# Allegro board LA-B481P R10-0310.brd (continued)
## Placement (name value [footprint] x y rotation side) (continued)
PR105  210K_0402_1%  [R_0402]  127.13 12.95 270 top
PR106  100K_0402_5%  [R_0402]  133.12 14.27 180 top
PR107  0_0603_5%  [R_0603]  134.46 17.09 180 top
PR108  0_0603_5%  [R_0603]  125.44 17.09 180 top
PR109  4.7_1206_5%  [R_1206]  136.17 24.78 270 top
PR110  4.7_1206_5%  [R_1206]  121.19 24.39 270 top
PR111  2.2_1206_1%  [R_1206]  127.37 21.66 0 top
PR112  0_0402_5%  [R_0402]  122.79 13 270 top
PR113  0_0402_5%  [R_0402]  122.76 13.03 270 bottom
PR114  0_0402_5%  [R_0402]  124.62 12.09 90 top
PR115  2.2K_0402_5%  [R_0402]  123.7 13 270 top
PR116  402K_0402_1%  [R_0402]  125.5 13 270 top
PR200  2.2_0603_5%  [R_0603]  153.64 24.19 90 bottom
PR201  21K_0402_1%  [R_0402]  157.37 21.52 90 bottom
PR202  4.7_1206_5%  [R_1206]  149.19 11.5 0 bottom
PR203  5.1_0603_5%  [R_0603]  160.87 21.27 90 bottom
PR204  8.06K_0402_1%  [R_0402]  160.24 29.45 180 bottom
PR205  887K_0402_1%  [R_0402]  161.76 24.57 180 bottom
PR206  10K_0402_1%  [R_0402]  160.25 30.35 180 bottom
PR207  0_0402_5%  [R_0402]  161.82 26.48 180 bottom
PR208  0_0402_5%  [R_0402]  161.79 28.36 180 bottom
PR209  2.2_0603_5%  [R_0603]  160.37 23.32 180 top
PR210  10K_0402_5%  [R_0402]  161.78 23.7 180 bottom
PR300  2.55K_0402_1%  [R_0402]  169.68 108.46 90 bottom
PR301  4.7_0603_5%  [R_0603]  167.71 113.87 90 bottom
PR302  15K_0402_1%  [R_0402]  172.7 108.66 180 bottom
PR303  1M_0402_1%  [R_0402]  168.72 109.37 270 bottom
PR304  20K_0402_1%  [R_0402]  171.78 110.69 0 bottom
PR305  1M_0402_1%  [R_0402]  48.49 90.88 180 bottom
PR306  4.7_0603_5%  [R_0603]  51.34 93.99 90 bottom
PR307  13.7K_0402_1%  [R_0402]  50.45 88.14 90 bottom
PR308  10K_0402_5%  [R_0402]  47.58 91.77 0 bottom
PR309  20K_0402_1%  [R_0402]  49.56 89.05 270 bottom
PR400  20K_0402_1%  [R_0402]  62.66 92.84 270 bottom
PR401  4.7_0603_5%  [R_0603]  64.61 87.4 270 bottom
PR402  40.2K_0402_1%  [R_0402]  59.69 92.54 0 bottom
PR403  1M_0402_1%  [R_0402]  63.59 91.9 90 bottom
PR404  20K_0402_1%  [R_0402]  60.63 90.64 180 bottom
PR409  51.1K_0402_1%  [R_0402]  172.52 154.61 270 bottom
PR410  17.8K_0402_1%  [R_0402]  172.74 144.4 90 bottom
PR411  100K_0402_1%  [R_0402]  170.49 153.69 90 bottom
PR412  20K_0402_1%  [R_0402]  170.96 145.31 270 bottom
PR500  2.61K_0402_1%  [R_0402]  165.43 139.27 0 top
PR501  499_0402_1%  [R_0402]  168.18 138.11 180 bottom
PR502  2K_0402_1%  [R_0402]  162.59 139.98 270 top
PR503  137K_0402_1%  [R_0402]  163.47 137.21 90 bottom
PR504  2.05K_0402_1%  [R_0402]  166.14 137.23 90 bottom
PR505  2K_0402_1%  [R_0402]  165.18 139.03 180 bottom
PR506  0_0603_5%  [R_0603]  142.27 141.11 90 top
PR507  226_0402_1%  [R_0402]  161.65 139.01 180 top
PR508  21K_0402_1%  [R_0402]  162.58 137.21 90 bottom
PR509  11K_0402_1%  [R_0402]  164.69 138.13 270 top
PR510  1.91K_0402_1%  [R_0402]  161.57 139.09 270 bottom
PR511  2.2_0603_5%  [R_0603]  160.47 138.04 180 bottom
PR512  4.7_0603_5%  [R_0603]  136.93 140.73 270 top
PR513  3.65K_0603_1%  [R_0603]  166.14 141.62 270 top
PR514  61.9K_0402_1%  [R_0402]  164.28 132.84 0 top
PR515  3.83K_0402_1%  [R_0402]  167.97 135.97 180 bottom
PR516  0_0402_5%  [R_0402]  168 134.95 180 bottom
PR518  0_0603_5%  [R_0603]  158.21 134.31 180 bottom
PR519  1_0603_5%  [R_0603]  156.74 131.35 0 bottom
PR520  20_0402_1%  [R_0402]  167.93 133.77 180 bottom
PR521  16.9_0402_1%  [R_0402]  167.93 132.88 180 bottom
PR522  1.91K_0402_1%  [R_0402]  157.97 132.92 180 bottom
PR523  3.83K_0402_1%  [R_0402]  167 131.1 0 bottom
PR524  0_0402_5%  [R_0402]  167.92 129.31 180 bottom
PR525  499_0402_1%  [R_0402]  167.03 131.1 90 top
PR526  73.2_0402_1%  [R_0402]  167.93 132.88 180 top
PR527  73.2_0402_1%  [R_0402]  167.93 133.77 180 top
PR528  0_0603_5%  [R_0603]  156.73 125.7 180 top
PR529  61.9K_0402_1%  [R_0402]  167.92 130.2 180 bottom
PR530  1.91K_0402_1%  [R_0402]  161.69 128.44 270 bottom
PR531  2.2_0603_5%  [R_0603]  160.72 127.8 180 bottom
PR532  4.7_0603_5%  [R_0603]  153.86 121.38 180 top
PR533  2K_0402_1%  [R_0402]  164.35 126.65 0 bottom
PR534  64.9K_0402_1%  [R_0402]  162.58 127.52 90 bottom
PR535  2.61K_0402_1%  [R_0402]  165.64 127.66 270 top
PR536  3.65K_0603_1%  [R_0603]  166.78 126.5 90 top
PR538  499_0402_1%  [R_0402]  167.11 128.34 180 bottom
PR539  2K_0402_1%  [R_0402]  160.68 127.15 270 top
PR540  191_0402_1%  [R_0402]  161.57 127.15 270 top
PR541  11K_0402_1%  [R_0402]  164.75 127.66 270 top
PR542  1.78K_0402_1%  [R_0402]  167.11 127.33 180 bottom
PR543  137K_0402_1%  [R_0402]  165.26 127.54 180 bottom
PR700  0.01_1206_1%  [R_1206_4P-D]  147.6 159.04 270 bottom
PR701  200K_0402_1%  [R_0402]  143.67 160.3 270 top
PR702  200K_0402_1%  [R_0402]  136.68 163.6 270 top
PR703  150K_0402_1%  [R_0402]  142.78 159.38 90 top
PR704  10_0402_5%  [R_0402]  167.64 167.49 180 top
PR705  10_0402_5%  [R_0402]  167.64 166.6 180 top
PR706  200K_0402_1%  [R_0402]  170.07 164.72 90 top
PR707  10_1206_1%  [R_1206]  164.79 177.24 0 top
PR708  47K_0402_1%  [R_0402]  170.06 162.94 90 top
PR709  4.7_0603_5%  [R_0603]  168.11 177.11 180 bottom
PR710  100K_0402_1%  [R_0402]  176 174.45 180 top
PR711  232K_0402_1%  [R_0402]  170.06 167.41 270 top
PR712  200K_0402_5%  [R_0402]  141.33 159.59 180 top
PR713  0_0603_5%  [R_0603]  164.81 173.05 0 bottom
PR714  100K_0402_1%  [R_0402]  173.89 164.74 270 top
PR715  49.9K_0402_1%  [R_0402]  171.17 170.46 270 bottom
PR716  158K_0402_1%  [R_0402]  175.09 173.43 0 top
PR717  0_0402_5%  [R_0402]  176 171.91 180 top
PR718  10K_0402_5%  [R_0402]  143.69 165 270 top
PR719  0_0402_5%  [R_0402]  176 171.02 180 top
PR720  0.01_1206_1%  [R_1206_4P-D]  149.8 181.86 0 bottom
PR721  4.7_1206_5%  [R_1206]  149.48 174.03 270 bottom
PR722  100_0402_1%  [R_0402]  176 170.08 180 top
PR723  4.7K_0402_5%  [R_0402]  174.15 167.79 270 top
PR724  10_0402_5%  [R_0402]  172.7 178.51 180 top
PR725  221K_0402_1%  [R_0402]  172.24 166.88 90 top
PR726  100_0402_5%  [R_0402]  173.43 176.22 0 top
PR727  287K_0402_1%  [R_0402]  171.22 166.88 90 top
PR728  28.7K_0402_1%  [R_0402]  173.26 166.88 90 top
PR729  63.4K_0402_1%  [R_0402]  172.19 165.94 180 top
PR730  3.3K_1206_5%~D  [R_1206]  133.38 163.84 270 top
PU100  -  [TPS51225CRUKR_QFN20_3X3]  128.43 14.55 0 top
PU200  -  [RT8207MZQW_WQFN20_3X3]  156.49 27.62 0 bottom
PU300  -  [SY8032ABC_SOT23-6]  168.02 110.63 90 bottom
PU301  -  [SY8032ABC_SOT23-6]  49.88 92.59 0 bottom
PU400  -  [SY8032ABC_SOT23-6]  64.29 90.64 270 bottom
PU402  -  [APL5930KAI-TRG_SO8]  172.23 146.89 180 bottom
PU500  -  [ISL95833HRTZ-T_TQFN32_4X4]  165.12 134.24 270 bottom
PU700  ISL88731CHRTZ-T TQFN 28P PWM  [BQ24745RHDR_QFN28_5X5]  169.39 169.89 0 top
Q8  -  [2N7002K_SOT23-3]  163.71 22.68 270 top
Q14  -  [DMN66D0LDW-7_SOT363-6]  14.78 112.66 180 bottom
Q50  -  [2N7002K_SOT23-3]  175.01 69.29 270 top
Q57  -  [MESS138W-G_SOT323-3]  18 110.18 90 top
Q58  -  [MESS138W-G_SOT323-3]  18 107.77 90 top
Q70  -  [2N7002K_SOT23-3]  65.46 101.37 270 bottom
Q71  -  [2N7002K_SOT23-3]  65.46 97.31 270 bottom
Q2307  -  [2N7002K_SOT23-3]  156.98 33.35 270 top
Q2308  -  [2N7002K_SOT23-3]  68.99 29.77 0 top
Q2309  -  [DMN66D0LDW-7_SOT363-6]  208.42 157.23 0 bottom
QA5  -  [DMN66D0LDW-7_SOT363-6]  29.25 17.95 180 top
QA6  -  [DMN66D0LDW-7_SOT363-6]  27.61 14.48 270 top
QC1  -  [MESS138W-G_SOT323-3]  126.84 123.77 90 top
QC2  -  [MESS138W-G_SOT323-3]  106.71 139.33 0 top
QC3  -  [MESS138W-G_SOT323-3]  118.39 136.79 0 top
QC4  -  [MESS138W-G_SOT323-3]  120.93 136.79 0 top
QD18  -  [2N7002K_SOT23-3]  57.9 16.58 90 top
QD19  -  [2N7002K_SOT23-3]  61.48 16.6 270 top
QD20  -  [2N7002K_SOT23-3]  68.46 16.58 270 top
QM30  -  [2N7002K_SOT23-3]  102.42 147.33 90 top
QS2  SI3456BDV-T1-E3 1N TSOP6  [SI3456BDV-T1-E3_TSOP6]  222.35 108.04 90 top
QS3  -  [2N7002KW_SOT323-3]  222.19 107.77 270 bottom
QX1  -  [2N7002KW_SOT323-3]  214.32 176.48 90 top
QX2  -  [SI3457CDV-T1-GE3_TSOP6]  221.59 175.15 90 top
QX6  -  [DMN66D0LDW-7_SOT363-6]  198.85 156.17 270 top
R3  4.7K_0402_5%  [R_0402]  78.96 87.31 90 top
R4  4.7K_0402_5%  [R_0402]  80.36 95.02 270 top
R5  4.7K_0402_5%  [R_0402]  97.93 143.19 0 top
R6  4.7K_0402_5%  [R_0402]  82.77 95.02 270 top
R7  4.7K_0402_5%  [R_0402]  77.88 95.02 270 top
R8  4.7K_0402_5%  [R_0402]  102.34 138.95 180 top
R10  100K_0402_5%  [R_0402]  161.7 22.22 90 top
R13  4.7K_0402_5%  [R_0402]  79.12 84.95 0 top
R14  4.7K_0402_5%  [R_0402]  73.5 84.2 90 top
R15  0_0402_5%  [R_0402]  60.67 84.29 270 top
R16  100K_0402_5%  [R_0402]  167.54 22.22 90 top
R17  0_0402_5%  [R_0402]  59.66 81.6 90 top
R18  0_0402_5%  [R_0402]  82.27 85.08 180 top
R19  0_0402_5%  [R_0402]  81.37 84.14 0 top
R20  0_0402_5%  [R_0402]  74.82 84.73 0 top
R21  0_0402_5%  [R_0402]  76.79 83.84 180 top
R121  100K_0402_5%  [R_0402]  14.18 111.58 0 bottom
R122  100K_0402_5%  [R_0402]  14.18 115.64 0 bottom
R376  10K_0402_5%  [R_0402]  15.9 113.66 90 bottom
R377  10K_0402_5%  [R_0402]  208.44 153.41 90 bottom
R378  10K_0402_5%  [R_0402]  99.39 94.82 0 top
R379  10K_0402_5%  [R_0402]  106.45 134.49 90 top
R380  10K_0402_5%  [R_0402]  107.34 134.49 90 top
R432  0_0402_5%  [R_0402]  109.93 145.74 0 top
R434  0_0402_5%  [R_0402]  109.93 146.76 0 top
R488  10K_0402_5%  [R_0402]  189.39 47.88 90 top
R489  10K_0402_5%  [R_0402]  190.66 44.96 90 top
R696  10K_0402_5%  [R_0402]  177.02 61.03 180 top
R697  10K_0402_5%  [R_0402]  178.79 64.97 180 top
R926  120K_0402_5%  [R_0402]  109.12 31.27 270 bottom
R927  100K_0402_5%  [R_0402]  106.07 30.35 90 bottom
R1022  0_0603_5%  [R_0603]  99.15 123.01 180 top
R1023  0_0603_5%  [R_0603]  122.52 123.39 0 top
R1024  10K_0402_5%  [R_0402]  81.26 89.24 180 top
R1027  4.7K_0402_1%  [R_0402]  83.98 66.93 90 top
R1028  4.7K_0402_1%  [R_0402]  84.99 66.93 90 top
R1029  4.7K_0402_1%  [R_0402]  124.72 57.77 90 top
R1030  4.7K_0402_1%  [R_0402]  123.7 57.77 90 top
R1033  10K_0402_5%  [R_0402]  74.2 89.22 90 top
R1045  0_0603_5%  [R_0603]  57.88 51.48 180 top
R1046  10K_0402_5%  [R_0402]  56.04 60.4 270 top
R1047  100K_0402_5%  [R_0402]  51.84 50.01 90 top
R1048  2.7K_0402_1%  [R_0402]  48.44 53.29 180 top
R1049  100K_0402_5%  [R_0402]  54.89 50.01 90 top
R1050  10K_0402_5%  [R_0402]  53.88 50.01 90 top
R1051  10K_0402_5%  [R_0402]  56.04 57.53 90 top
R1052  470_0603_5%  [R_0603]  67.53 97.31 0 bottom
R1055  82K_0402_5%  [R_0402]  60.02 101.29 0 top
R1056  47K_0402_5%  [R_0402]  60.02 104.34 0 top
R1061  10K_0402_5%  [R_0402]  67.21 102.94 90 bottom
R1071  619_0402_1%  [R_0402]  16.11 101.67 180 top
R1072  619_0402_1%  [R_0402]  16.11 100.66 180 top
R1073  619_0402_1%  [R_0402]  15.85 104.47 180 top
R1074  619_0402_1%  [R_0402]  15.85 103.45 180 top
R1075  619_0402_1%  [R_0402]  16.11 98.88 180 top
R1076  619_0402_1%  [R_0402]  16.11 97.86 180 top
R1077  619_0402_1%  [R_0402]  16.11 95.83 180 top
R1078  619_0402_1%  [R_0402]  16.11 94.82 180 top
R1088  0_0402_5%  [R_0402]  88.11 107.57 135 bottom
R1089  0_0402_5%  [R_0402]  88.86 107.07 45 bottom
R2314  22_0603_5%  [R_0603]  146.02 61.03 180 top
R2315  470_0603_5%  [R_0603]  66.2 31.25 270 top
R2354  0_0402_5%  [R_0402]  186.72 47.88 90 top
R2355  0_0402_5%  [R_0402]  44.22 26.79 90 top
RA1  100K_0402_5%  [R_0402]  27.96 23.98 270 top
RA2  100K_0402_5%  [R_0402]  30.6 23.99 270 top
RA3  10K_0402_5%  [R_0402]  27.46 20.6 270 top
RA4  0_0402_5%  [R_0402]  26.57 20.6 270 top
RA5  470K_0402_5%  [R_0402]  32.16 25.3 270 top
RA6  10K_0402_5%  [R_0402]  29.71 23.98 270 top
RA7  10K_0402_5%  [R_0402]  28.83 23.98 270 top
RA8  0_0402_5%  [R_0402]  51.73 18.55 180 top
RA9  0_0402_5%  [R_0402]  51.73 17.6 180 top
RA10  0_0402_5%  [R_0402]  33.94 25.3 270 top
RA12  0_0402_5%  [R_0402]  33.05 25.3 270 top
RA19  10K_0402_5%  [R_0402]  192.51 46.05 180 top
RA28  0_0402_5%  [R_0402]  36.3 19 180 top
RA29  0_0603_5%  [R_0603]  23.02 20.97 90 top
RA30  0_0603_5%  [R_0603]  25.43 11.95 270 top
RA31  0_0603_5%  [R_0603]  25.94 23.06 90 top
RA32  0_0603_5%  [R_0603]  35.21 12.84 270 top
RA34  200K_0402_1%  [R_0402]  37.57 24.33 180 top
RA51  39.2K_0402_1%  [R_0402]  37.57 23.44 180 top
RA53  2.2K_0402_5%  [R_0402]  37.01 21.28 180 top
RA55  8.2_0402_1%  [R_0402]  24.74 14.93 180 bottom
RA56  8.2_0402_1%  [R_0402]  24.74 18.24 180 bottom
RA79  1K_0402_1%  [R_0402]  41.05 28.52 90 top
RA80  1K_0402_1%  [R_0402]  35.87 15.26 270 top
RA81  10K_0402_5%  [R_0402]  40.1 26.67 90 top
RA82  1K_0402_1%  [R_0402]  34.97 15.26 270 top
RA83  10K_0402_5%  [R_0402]  23.83 15.82 0 bottom
RA84  10K_0402_5%  [R_0402]  23.83 17.35 0 bottom
RA130  22_0402_5%  [R_0402]  122.13 130.88 0 bottom
RA153  20K_0402_1%  [R_0402]  34.88 23.44 0 top
RA154  100K_0402_5%  [R_0402]  39.53 15.11 90 top
RA155  100K_0402_5%  [R_0402]  38.51 24.38 90 top
RA165  4.7K_0402_5%  [R_0402]  44.62 15.77 270 top
RA166  4.7K_0402_5%  [R_0402]  43.74 15.77 270 top
RA1109  2.2K_0402_5%  [R_0402]  37.01 22.3 180 top
RC1  100K_0402_5%  [R_0402]  121.22 110.47 135 top
RC2  100K_0402_5%  [R_0402]  121.85 111.11 135 top
RC3  23.2_0402_1%  [R_0402]  119.95 109.2 135 top
RC4  29.4_0402_1%  [R_0402]  120.58 109.84 135 top
RC5  162_0402_1%  [R_0402]  119.31 108.57 135 top
RC6  4.7K_0402_1%  [R_0402]  126.04 105.7 90 bottom
RC7  4.7K_0402_1%  [R_0402]  125.15 105.7 90 bottom
RC8  2.2K_0402_5%  [R_0402]  108.48 109.4 225 top
RC9  402_0402_1%  [R_0402]  108.94 123.71 225 top
RC10  10K_0402_5%  [R_0402]  100.3 102.11 135 bottom
RC11  10K_0402_5%  [R_0402]  100.42 103.52 315 bottom
RC12  402_0402_1%  [R_0402]  112.28 123.64 45 top
RC13  402_0402_1%  [R_0402]  110.21 123.7 135 top
RC14  49.9_0402_1%  [R_0402]  120.48 128.91 45 bottom
RC15  33.2_0402_1%  [R_0402]  95.98 105.68 225 bottom
RC16  10K_0402_5%  [R_0402]  119.1 120.94 135 top
RC17  10K_0402_5%  [R_0402]  125.76 122.43 90 top
RC18  10K_0402_5%  [R_0402]  105.87 136.35 0 top
RC19  1M_0402_5%  [R_0402]  101.06 128.41 225 bottom
RC20  4.7K_0402_5%  [R_0402]  64.16 84.1 270 top
RC21  2.2K_0402_5%  [R_0402]  99.65 110 315 top
RC22  47.5_0402_1%  [R_0402]  103.09 122.15 315 top
RC23  4.02K_0402_1%  [R_0402]  104.29 120.88 315 top
RC24  0_0402_5%  [R_0402]  114.27 135.39 135 bottom
RC25  200_0402_5%  [R_0402]  101.02 111.36 135 top
RC26  100K_0402_5%  [R_0402]  92.48 113.31 270 top
RC27  73.2_0402_1%  [R_0402]  94.96 102.37 45 bottom
RC28  20_0402_1%  [R_0402]  96.87 104.28 225 bottom
RC29  16.9_0402_1%  [R_0402]  98.9 106.06 225 bottom
RC30  10K_0402_5%  [R_0402]  85.04 85.93 0 top
RC31  10M_0402_5%  [R_0402]  90.84 115.31 315 bottom
RC32  49.9_0402_1%  [R_0402]  105.49 113.74 0 top
RC33  1K_0402_5%  [R_0402]  183.04 110.01 270 bottom
RC34  20K_0402_1%  [R_0402]  87.51 109.54 315 bottom
RC35  20K_0402_1%  [R_0402]  91.91 111.27 315 bottom
RC36  3.3K_0402_5%  [R_0402]  70.06 82.37 0 top
RC37  3.3K_0402_5%  [R_0402]  83.67 80.59 180 top
RC38  3.3K_0402_5%  [R_0402]  70.06 80.59 0 top
RC39  33_0402_5%  [R_0402]  82.76 79.58 0 top
RC40  1.24K_0402_1%  [R_0402]  101.76 119.64 45 top
RC41  1K_0402_1%  [R_0402]  96.64 114.21 45 top
RC42  1K_0402_1%  [R_0402]  98.64 115.57 45 top
RC43  10K_0402_5%  [R_0402]  112.47 136.22 0 top
RC44  10K_0402_5%  [R_0402]  93.19 107.84 225 bottom
RC45  45.3_0402_1%  [R_0402]  98.9 117.75 225 top
RC46  10K_0402_5%  [R_0402]  94.19 108.84 45 bottom
RC47  0_0402_5%  [R_0402]  103.03 119.66 225 top
RC48  10K_0402_5%  [R_0402]  113.39 135.33 180 top
RC49  45.3_0402_1%  [R_0402]  89.06 118.95 315 bottom
RC50  49.9_0402_1%  [R_0402]  114.58 135.53 270 top
RC51  22_0402_5%  [R_0402]  120.49 134 225 bottom
RC52  22_0402_5%  [R_0402]  119.73 134.64 225 bottom
RC53  4.7K_0402_5%  [R_0402]  103.71 138.63 0 top
RC54  0_0402_5%  [R_0402]  118.77 113.87 0 top
RC55  100_0402_1%  [R_0402]  108.23 135.41 270 top
RC56  100_0402_1%  [R_0402]  108.74 113.05 270 top
RC57  49.9_0402_1%  [R_0402]  107.67 124.53 180 top
RC58  100_0402_1%  [R_0402]  106.52 109.73 135 top
RC59  49.9_0402_1%  [R_0402]  123.28 126.24 45 bottom
RC60  10K_0402_5%  [R_0402]  119.28 131.54 225 bottom
RC61  200_0402_5%  [R_0402]  54 80.54 270 top
RC62  1K_0402_5%  [R_0402]  63.15 81.3 270 top
RC63  51_0402_5%  [R_0402]  65.18 81.3 270 top
RC64  51_0402_5%  [R_0402]  101.94 112.4 45 top
RC65  51_0402_5%  [R_0402]  100.39 110.72 135 top
RC66  33_0402_5%  [R_0402]  123.58 128.25 225 bottom
RC67  100K_0402_5%  [R_0402]  102.85 97.99 180 top
RC68  10K_0402_5%  [R_0402]  127.98 122.83 315 bottom
RC69  33_0402_5%  [R_0402]  122.32 129.51 225 bottom
RC70  33_0402_5%  [R_0402]  122.96 128.87 225 bottom
RC71  33_0402_5%  [R_0402]  126.62 126.74 135 bottom
RC99  0_0402_1%  [R0402_0OHM]  82.76 81.61 0 top
RC100  0_0402_1%  [R0402_0OHM]  110.62 113.21 225 top
RD3  470_0402_5%  [R_0402]  93.6 60.82 90 top
RD4  0_0402_1%  [R0402_0OHM]  124.72 61.73 270 top
RD5  0_0402_1%  [R0402_0OHM]  92.59 60.82 90 top
RD6  10K_0402_5%  [R_0402]  143.44 68.77 0 top
RD7  10K_0402_5%  [R_0402]  143.44 69.78 0 top
RD8  0_0402_1%  [R0402_0OHM]  122.1 64.7 0 top
RD9  0_0402_1%  [R0402_0OHM]  122.43 63.31 0 top
RD14  680_0402_1%  [R_0402]  34.27 10.49 180 top
RD15  390_0402_5%  [R_0402]  43.98 10.74 180 top
RD17  390_0402_5%  [R_0402]  50.52 11.89 180 top
RD18  680_0402_1%  [R_0402]  57.93 12.9 0 top
RD45  100K_0402_5%  [R_0402]  59.16 22.55 180 top
RD46  100K_0402_5%  [R_0402]  58.82 13.9 180 top
RD47  100K_0402_5%  [R_0402]  65.32 16.33 90 top
RD48  0_0402_5%  [R_0402]  58.25 23.44 0 top
RD49  0_0402_5%  [R_0402]  60.68 18.11 180 top
RD50  100K_0402_5%  [R_0402]  72.55 15.62 90 top
RD51  0_0402_5%  [R_0402]  56.92 13.87 270 top
RD52  100K_0402_5%  [R_0402]  55.91 13.87 270 top
RD53  0_0402_5%  [R_0402]  73.56 15.62 90 top
RE1  10K_0402_5%  [R_0402]  175.21 57.22 0 top
RE3  100K_0402_1%  [R_0402]  192.48 71.32 0 top
RE4  0_0805_5%  [R_0805]  198.66 46.47 90 top
RE5  33K_0402_1%  [R_0402]  193.4 70.43 180 top
RE6  0_0805_5%  [R_0805]  196.88 46.47 90 top
RE7  0_0402_5%  [R_0402]  197.64 70.38 270 top
RE8  47K_0402_5%  [R_0402]  199.85 54.81 0 top
RE9  4.7K_0402_5%  [R_0402]  186.59 70.38 270 top
RE10  4.7K_0402_5%  [R_0402]  185.58 70.38 270 top
RE11  100K_0402_5%  [R_0402]  179.18 49.86 180 top
RE12  0_0402_5%  [R_0402]  178.92 55.07 180 top
RE13  0_0402_5%  [R_0402]  176 64.59 180 top
RE14  0_0402_5%  [R_0402]  189.64 44.96 90 top
RE15  0_0402_5%  [R_0402]  190.15 70.38 270 top
RE16  0_0402_5%  [R_0402]  189.13 70.38 270 top
RE17  0_0402_5%  [R_0402]  156.7 81.1 180 top
RE18  10K_0402_5%  [R_0402]  195.48 48.79 270 top
RE19  0_0402_5%  [R_0402]  159.49 81.1 180 top
RE20  0_0402_5%  [R_0402]  162.28 81.1 180 top
RE21  0_0402_5%  [R_0402]  165.08 81.1 180 top
RE36  43_0402_1%  [R_0402]  178.01 61.92 0 top
RE37  0_0402_1%  [R0402_0OHM]  187.99 70.38 270 top
RE43  43_0402_1%  [R_0402]  178.92 56.72 180 top
RE44  0_0402_1%  [R0402_0OHM]  176 65.61 180 top
RE47  100K_0402_5%  [R_0402]  178.21 63.78 270 top
RE49  100K_0402_5%  [R_0402]  194.54 27.57 180 top
RE50  10K_0402_5%  [R_0402]  50.91 105.23 180 bottom
RE60  240_0402_1%  [R_0402]  227.99 156.33 90 bottom
RE71  10K_0402_5%  [R_0402]  176.94 59.08 270 top
RG1  330_0402_5%  [R_0402]  70.26 42.7 270 top
RG2  0_0402_5%  [R_0402]  64.67 42.7 270 top
RG5  33_0402_5%  [R_0402]  68.23 35.58 270 top
RG6  0_0402_5%  [R_0402]  67.21 35.58 270 top
RG8  0_0402_5%  [R_0402]  70.26 34.67 90 top
RG10  0_0402_5%  [R_0402]  102.33 129.68 225 bottom
RG11  0_0402_5%  [R_0402]  35.97 75.82 90 bottom
RI1  0_0805_5%  [R_0805]  23.27 66.53 90 top
RI2  0_0805_5%  [R_0805]  26.19 51.72 270 bottom
RI3  0_0805_5%  [R_0805]  25.56 41.9 90 bottom
RI4  0_0805_5%  [R_0805]  23.31 64.97 0 top
RI5  0_0805_5%  [R_0805]  25.85 53.16 0 bottom
RI6  0_0805_5%  [R_0805]  25.47 37.41 0 bottom
RL19  75_0603_5%  [R_0603]  20.29 85.54 270 top
RL20  75_0603_5%  [R_0603]  20.29 81.73 90 top
RL27  100K_0402_5%  [R_0402]  48.97 79.32 0 bottom
RL28  0_0805_5%  [R_0805]  47.44 75.26 0 bottom
RL31  2.49K_0402_1%  [R_0402]  35.08 79.37 90 bottom
RL33  1K_0402_5%  [R_0402]  45.06 87.32 180 bottom
RL34  10K_0402_5%  [R_0402]  43.03 83.39 180 bottom
RL35  15K_0402_5%  [R_0402]  45.06 86.43 180 bottom
RL36  10K_0402_5%  [R_0402]  41.56 80.92 270 bottom
RL38  10K_0402_5%  [R_0402]  49.89 78.43 180 bottom
RL40  10K_0402_5%  [R_0402]  50.7 80.52 90 bottom
RM11  100K_0402_5%  [R_0402]  115.09 147.7 90 top
RM13  1K_0402_1%  [R_0402]  115.98 148.61 270 top
RM25  0_0805_1%  [R0805_0OHM]  120.16 147.98 180 top
RM26  0_0805_1%  [R0805_0OHM]  96 148.47 180 top
RM110  10K_0402_5%  [R_0402]  104.17 148.68 270 top
RP15  2.2K_0804_8P4R_5%  [RP_0804_8P4R]  18.71 111.65 270 bottom
RP36  2.2K_0804_8P4R_5%  [RP_0804_8P4R]  189.4 72.27 90 top
RP54  8.2K_8P4R_5%  [RP_0804_8P4R]  123.1 135.13 90 top
RP56  2.2K_8P4R_5%  [RP_0804_8P4R]  210.78 162.01 0 bottom
RP63  10K_0804_8P4R_5%  [RP_0804_8P4R]  109.77 135.39 90 top
RP65  10K_0804_8P4R_5%  [RP_0804_8P4R]  104.03 109.74 270 top
RP66  51_0804_8P4R_5%  [RP_0804_8P4R]  98.06 113.39 45 top
RP67  22_0804_8P4R_5%  [RP_0804_8P4R]  96.55 107.09 45 bottom
RP68  4.7K_0804_8P4R_5%  [RP_0804_8P4R]  117.25 134.52 45 bottom
RR1  6.19K_0402_1%  [R_0402]  175.21 18.08 270 top
RR2  22_0402_5%  [R_0402]  178.21 27.11 90 top
RR3  22_0402_5%  [R_0402]  180.88 20.94 0 top
RS6  470K_0402_5%  [R_0402]  222.36 105.74 180 bottom
RS7  0_0402_5%  [R_0402]  220.68 53.92 0 bottom
RS8  0_0402_5%  [R_0402]  220.68 52.91 0 bottom
RS9  100K_0402_5%  [R_0402]  216.36 115.77 0 top
RS09  0_0402_5%  [R_0402]  221.44 112.09 0 bottom
RS10  0_0402_5%  [R_0402]  221.44 117.17 0 bottom
RS11  0_0805_5%  [R_0805]  217.96 113.83 270 top
RS12  0_0805_5%  [R_0805]  219.74 113.83 270 top
RT1  0_0805_1%  [R0805_0OHM]  198.75 169.87 180 bottom
RT2  4.7K_0402_5%  [R_0402]  210.72 156.16 270 bottom
RT3  4.7K_0402_5%  [R_0402]  210.72 157.4 90 bottom
RT9  0_0402_5%  [R0402_0OHM]  200.44 157.67 90 bottom
RT11  0_0402_5%  [R0402_0OHM]  199.55 157.67 90 bottom
RT12  4.7K_0402_5%  [R_0402]  211.74 157.4 90 bottom
RT14  0_0402_5%  [R_0402]  195.18 164.16 180 bottom
RT15  0_0402_5%  [R_0402]  195.18 165.05 180 bottom
RT16  100K_0402_5%  [R_0402]  208.23 158.32 0 bottom
RT17  100K_0402_5%  [R_0402]  207.29 155.32 90 bottom
RT18  100K_0402_5%  [R_0402]  206.28 156.23 270 bottom
RT19  100K_0402_5%  [R_0402]  202.64 165.17 0 top
RT20  4.7K_0402_5%  [R_0402]  211.74 156.16 270 bottom
RT21  0_0402_5%  [R_0402]  200.44 156.68 270 bottom
RT22  0_0402_5%  [R_0402]  199.55 156.68 270 bottom
RT331  0_0603_5%  [R_0603]  194.97 161.3 90 bottom
RV31  0_0402_5%  [R_0402]  210.47 176.02 90 top
RV32  0_0402_5%  [R_0402]  211.48 176.02 90 top
RV54  0_0603_1%  [R0603_0OHM]  50.57 25.09 180 top
RV59  0_0603_1%  [R0603_0OHM]  36.6 11.44 90 top
RV299  0_0805_5%  [R_0805]  215.67 158.61 90 bottom
RV300  0_0805_5%  [R_0805]  214.32 168.1 0 bottom
RV301  0_0805_5%  [R_0805]  223.08 175.59 0 top
RX1  0_0402_5%  [R_0402]  18.7 93.09 90 top
RX2  100K_0402_5%  [R_0402]  216.44 176.53 90 top
RX3  100K_0402_5%  [R_0402]  215.55 177.44 270 top
RX4  0_0402_5%  [R_0402]  193.07 55.37 90 bottom
RX5  12K_0402_1%  [R_0402]  201.7 158.37 90 bottom
RX6  3.3K_0402_5%  [R_0402]  202.64 164.29 0 top
RX7  0_0402_5%  [R_0402]  218.47 163.83 90 bottom
RX8  0_0402_5%  [R_0402]  218.47 162.84 270 bottom
RX9  10K_0402_5%  [R_0402]  221.34 172.79 180 top
RX12  10K_0402_5%  [R_0402]  15.09 110.56 180 bottom
RX18  0_0402_5%  [R_0402]  213.47 172.79 180 top
RX19  0_0402_1%  [R0402_0OHM]  214.33 172.79 0 top
RX20  0_0402_1%  [R0402_0OHM]  212.55 173.81 0 top
RX21  0_0402_5%  [R_0402]  218.65 167.1 90 bottom
RX22  0_0402_5%  [R_0402]  217.76 167.1 90 bottom
RX23  0_0402_5%  [R_0402]  215.24 173.81 180 top
RX24  100K_0402_5%  [R_0402]  19.71 93.09 90 top
RX26  100K_0402_5%  [R_0402]  221.34 173.81 180 top
RX27  0_0603_1%  [R0603_0OHM]  216.75 173.3 0 top
RX28  0_0603_5%  [R_0603]  25.05 93.61 90 bottom
RX29  0_0603_5%  [R_0603]  26.57 93.61 90 bottom
RX33  100K_0402_5%  [R_0402]  192.56 166.19 90 bottom
RX36  100K_0402_5%  [R_0402]  204.5 166.01 270 top
SW1  SMT1-05-A_4P  [SW_SMT1-05-A_4P]  196.77 27.43 90 top
SW2  SMT1-05-A_4P  [SW_SMT1-05-A_4P]  202.92 39.99 180 bottom
T94  PAD~D  [TPC12]  41.3 78.64 180 bottom
T95  PAD~D  [TPC12]  40.29 81.1 180 bottom
T97  PAD  [TPC12]  102.33 104.9 180 bottom
T98  PAD  [TPC12]  103.23 105.84 180 bottom
T100  PAD  [TPC12]  120.53 127.15 180 bottom
T101  PAD  [TPC12]  118.05 129.6 180 bottom
T102  PAD  [TPC12]  115.93 124.79 0 top
T103  PAD  [TPC12]  103.78 111.15 90 top
T104  PAD  [TPC12]  104.54 113.78 90 top
T105  PAD  [TPC12]  98.94 109.12 270 bottom
T106  PAD  [TPC12]  112.17 127.73 0 top
T107  PAD  [TPC12]  114.3 127.19 0 top
T108  PAD  [TPC12]  123.09 125.17 270 bottom
T109  PAD  [TPC12]  124.64 126.15 270 bottom
T110  PAD  [TPC12]  125.25 124.79 270 bottom
T111  PAD  [TPC12]  123.85 123.9 270 bottom
T112  PAD  [TPC12]  107.32 115.93 90 top
T113  PAD  [TPC12]  12.98 60.65 180 bottom
T114  PAD  [TPC12]  12.98 62.05 180 bottom
T115  PAD  [TPC12]  14.63 62.18 180 bottom
T116  PAD  [TPC12]  14.63 63.45 180 bottom
T192  PAD  [TPC12]  190.74 46.94 0 top
T194  PAD  [TPC12]  185.96 71.45 0 top
T195  PAD  [TPC12]  112.2 116.49 90 top
T196  PAD  [TPC12]  185.16 68.46 0 top
T199  PAD  [TPC12]  154.84 81.1 0 top
T200  PAD  [TPC12]  157.64 81.1 0 top
T201  PAD  [TPC12]  160.43 81.1 0 top
T202  PAD  [TPC12]  163.22 81.1 0 top
T203  PAD  [TPC12]  177.83 57.64 0 top
T204  PAD  [TPC12]  198.96 52.96 0 top
T207  PAD  [TPC12]  197.53 71.37 0 top
T209  PAD  [TPC12]  177.09 54.52 0 top
T210  PAD  [TPC12]  179.8 54.89 0 top
T211  PAD  [TPC12]  120.7 135.19 180 bottom
T212  PAD  [TPC12]  187.99 71.45 0 top
T215  PAD  [TPC12]  180.11 51.64 0 top
T216  PAD  [TPC12]  201.7 53.1 0 top
T218  PAD  [TPC12]  178.03 61.03 0 top
T220  PAD  [TPC12]  179.63 57.63 0 top
T221  PAD  [TPC12]  179.33 61.03 0 top
TL1  NS681610_16P  [BOTH_NS0013LF_16P]  30.91 88.15 270 bottom
U11  -  [TPS22966DPUR_SON14_2X3]  105.13 28.28 0 bottom
U54  NL17SZ07DFT2G_SC70-5  [SN74LVC1G07DCKR_SC70-5]  81.58 88 180 top
U57  NL17SZ07DFT2G_SC70-5  [SN74LVC1G07DCKR_SC70-5]  74.85 88 180 top
U58  FE1.1S-BQFN24B_WQFN24_4X4  [FE1P1S-BQFN24B_WQFN24_4X4]  53.09 57.31 180 top
U59  -  [TPS22966DPUR_SON14_2X3]  58.46 101.87 90 top
U60  ME4856_SO8  [AO4304L_SO8]  72.42 99.35 180 bottom
U61  NL17SZ07DFT2G_SC70-5  [SN74LVC1G07DCKR_SC70-5]  76.66 86.26 0 top
U62  NL17SZ07DFT2G_SC70-5  [SN74LVC1G07DCKR_SC70-5]  79.07 91.22 0 top
U63  NL17SZ07DFT2G_SC70-5  [SN74LVC1G07DCKR_SC70-5]  81.55 91.22 0 top
U64  -  [G2129TL1U_SC70-6]  99.59 140.84 90 top
U65  NL17SZ07DFT2G_SC70-5  [SN74LVC1G07DCKR_SC70-5]  76.59 91.22 0 top
U66  NL17SZ07DFT2G_SC70-5  [SN74LVC1G07DCKR_SC70-5]  100.34 137.73 90 top
UA1  ALC3223-CG_MQFN48_6X6~D  [ALC3221-CG_MQFN48_6X6]  45.41 24.32 180 top
UC4  NL17SZ07DFT2G_SC70-5  [SN74LVC1G07DCKR_SC70-5]  102.66 96.83 180 top
UC5  NL17SZ07DFT2G_SC70-5  [SN74LVC1G07DCKR_SC70-5]  60.72 80.48 0 top
UC7  NL17SZ07DFT2G_SC70-5  [SN74LVC1G07DCKR_SC70-5]  89.8 84.39 90 top
UC8  -  [W25Q64DWSSIG_SO8]  73.24 82.24 270 top
UC10  NL17SZ07DFT2G_SC70-5  [SN74LVC1G07DCKR_SC70-5]  103.52 135.48 0 top
UD1  -  [MC74VHC1G08DFT2G_SC70-5]  59.53 19.24 90 top
UE1  KB9012QF-A4_LQFP128_14X14  [KB9012QF-A2_LQFP128_14X14]  183.19 51.17 0 top
UE2  -  [SN74LVC1G06DCKR_SC70-5]  176.79 62.16 90 top
UE3  APE8873M SOP 8P  [G993P1UF_SOP8]  46 102.35 0 bottom
UG1  SLG3NB244VTR _TQFN16_2X3  [SLG3NB274VTR_TQFN16_2X3]  65.5 37.66 0 top
UI1  -  [SY6288D20AAC_SOT23-5]  26.26 65.79 270 top
UI2  -  [AP2301MPG-13_MSOP8]  32.79 50.83 270 bottom
UI3  -  [AP2301MPG-13_MSOP8]  29.48 68.19 90 top
UI4  -  [SY6288D20AAC_SOT23-5]  28.8 53.1 90 bottom
UI5  -  [SY6288D20AAC_SOT23-5]  28.67 37.48 90 bottom
UI6  -  [AP2301MPG-13_MSOP8]  31.77 43.98 270 bottom
UI7  -  [SY6288D20AAC_SOT23-5]  216.37 112.28 90 top
UL1  -  [RTL8106E-CG_QFN32_4X4]  35.67 82.87 90 bottom
UL2  -  [APL3512ABI-TRG_SOT23-5]  43.78 74.92 180 bottom
UL3  -  [SY6288C20AAC_SOT23-5]  47.59 82.81 0 bottom
UR1  RTS5170-GR_QFN24_4X4  [RTS5179-GR_QFN24_4X4]  175.82 21.39 0 top
USOC1  FH8065301546401_FCBGA131170  [FH8065301546401_FCBGA13_1170P]  93.95 117.46 135 bottom
UT2  RTD2132N-CGT_QFN32_5X5  [RTD2132S-GR_QFN32_5X5]  207.21 160.74 180 bottom
UX1  -  [APL3512ABI-TRG_SOT23-5]  215.36 164.49 0 bottom
UX2  -  [MC74VHC1G08DFT2G_SC70-5]  195.8 167.35 270 bottom
Y9  12MHZ_12PF_5YEA12000122IFA2Q3  [Y_5YEA12000122IFA2Q3_4P]  53.33 59.98 180 bottom
YC1  25MHZ_10PF_7V25000014  [Y_7V25000014_4P]  99.45 130.68 225 bottom
YC2  32.768KHZ_12.5PF_Q13FC135000040  [Y_Q13FC135000040_2P]  87.28 113.61 315 bottom
YL2  25MHZ_10PF_7V25000014  [Y_FSX3M-25PM20FDO_4P]  37.41 78.09 0 bottom

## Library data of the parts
C182 C967 C976 C979 C980 C1034-C1055 C1058 C1060-C1074 C1076 C1078 C1117 C1118 C1121-C1128 C1131 C1138 C1139 C1143-C1148 CA21 CA22 CA24 CA25 CA29-CA33 CA38-CA40 CA51 CA54 CA56 CA58 CA60 CA65 CA69 CC1-CC32 CC39-CC47 CC49-CC65 CD1-CD11 CD21 CD22 CD24-CD27 CD30 CD31 CD63 CE1 CE2 CE5-CE9 CE11 CE12 CE15 CE18-CE20 CE23 CE24 CE26-CE31 CE33-CE36 CG1-CG4 CG7 CG10 CI2-CI4 CI7 CI9 CI10 CI13-CI15 CI17 CI26 CI28 CI29 CI34 CL15 CL19 CL20 CL22 CL26 CL30 CL31 CL34-CL37 CL39 CL41 CM40 CM46-CM48 CR1 CR3-CR7 CR9-CR11 CS5 CS6 CS8-CS11 CS13-CS15 CS17 CS105 CS106 CS108 CS109 CT2 CT3 CT5 CT7 CT8 CT10-CT12 CX1 CX2 CX4 CX6 CX9-CX19 CX21 CX23-CX30 CX42-CX44 CX46 PC1-PC9 PC11 PC106 PC107 PC109 PC110 PC203 PC204 PC211 PC212 PC214 PC215 PC301 PC304-PC306 PC309 PC310 PC401 PC404 PC405 PC411 PC413 PC415 PC502-PC508 PC511 PC512 PC514 PC516 PC520 PC521 PC523 PC525-PC529 PC531-PC535 PC701 PC704 PC708 PC712 PC715 PC716 PC721 PC723 PC725 PC727 PC923-PC928 PC933 PC934 = C_0402
C1056 C1057 C1059 C2307 CC36 CC38 CE16 CG5 CI6 CI11 CI12 CI18 CS7 CS12 CT6 CX3 CX7 CX8 CX20 CX51 PC108 PC111 PC118 PC205 PC206 PC208 PC209 PC509 PC510 PC519 PC522 PC702 PC703 PC717-PC720 PC902 PC904 PC906 PC908 = C_0805
C1119 C1120 C1129 C1130 C2305 C2306 C2308 C2316 C2318 C2323 C2324 CA1 CA2 CA23 CA53 CA55 CA57 CA59 CA61-CA64 CA67 CA68 CA71 CA74 CC33-CC35 CD12-CD14 CD16-CD20 CD28 CD29 CD62 CE22 CE25 CG6 CI40 CI43 CI45 CL38 CM43 CR2 CR8 CS16 CT1 CT4 CT9 CX5 CX22 CX50 PC105 PC112-PC117 PC207 PC210 PC213 PC300 PC302 PC303 PC307 PC308 PC311 PC400 PC402 PC403 PC412 PC414 PC513 PC515 PC517 PC518 PC524 PC530 PC700 PC705-PC707 PC709-PC711 PC713 PC714 PC722 PC726 PC901 PC903 PC905 PC907 PC913-PC916 PC920-PC922 PC929-PC932 = C_0603
CD15 CD32 PC909 PC911 PC917-PC919 = C_D2
CI1 CI8 CI33 = C_MP6VLPS220MC4R2
CL33 = C_1206
CLRP1 = SHORTPADS: User Part Number: PART#
DA8 = BAT54C-7-F_SOT23-3
DA10 DA12 = AZ5125-02SPR7G_SOT23-3
DC1 = RB751V40_SC76-2
DC3 = BAV70W-7-F_SOT323-3
DE1 = L03ESDL5V0CG3-2_SOT-523-3
DE3 = PESD5V0U2BT_SOT23-3
DI1 = IP4292CZ10-TBR_XSON10_2P5X1
DI2 DI8 DI9 = L30ESDL5V0C3-2_SOT23-3
DX1 = RB751V-40_SOD323-2
FD1-FD8 = FIDUCIAL_C40M80
FX1 = F_1206L150PR
H2 H4 H5 H8 H9 H11 H12 H16 H17 = H_2P8
H6 H7 H10 H18 = H_3P3
H31-H34 = H_3P7
H35 = H_3P7X3P2N
JBATT1 = LOTES_AAA-BAT-054-K01_2P
JDB1 = MOLEX_52435-2671_26P-T
JDIMM1 = LCN_DAN06-K4406-0102_204P
JFAN = ACES_85204-0300N_3P
JHDD = SANTA_193202-1_22P
JHDMI = LOTES_ABA-HDM-022-K01_19P
JHP = SINGA_2SJ-E960-001F_6P
JKB = HB_A823020-SBHR21_30P
JLAN = SANTA_130456-311_8P
JLVDS = STARC_107K40-000001-G2_40P
JMINI = CONCR_525B01BE17A_52P
JODD = SANTA_202801-1_13P
JP3-JP6 JP8 JP12 PJP202 PJP300-PJP302 PJP400 PJP401 PJP404 PJP405 = JUMP_43X39
JP7 JP13 JP38 JP39 PJP303 = JUMP_43X79
JP14 JP15 JP36 JP37 PJP1 PJP100 PJP101 PJP200 PJP201 = JUMP_43X118
JPWR = HB_A090420-SAHR21_4P
JREAD = T-SOL_143-2300302602_22P_RV
JSPK = E-T_3703-Q04N-11R_4P
JTOUCH = ACES_88460-00601-P01_6P
JTP = PS_HPF10052-06M000R_6P
JUSB1 JUSB7 JUSB8 = ACON_UARBG-4K1926_4P
L1 = MURAT_BLM15AG601SN1D_2P
LA1 = MURAT_BLM15BB221SN1D_2P
LA3-LA6 PR107 PR108 PR200 PR203 PR209 PR301 PR306 PR401 PR506 PR511-PR513 PR518 PR519 PR528 PR531 PR532 PR536 PR709 PR713 R1022 R1023 R1045 R1052 R2314 R2315 RA29-RA32 RL19 RL20 RT331 RX28 RX29 = R_0603
LA7-LA10 = CHILI_NBQ100505T-800Y-N_2P
LE1 LE2 = KC_FBMA-L11-160808-800LMT_2P
LED1 = LED_HT-210UD5-BP5_3P
LED2 LED4 = LED_12-21C-T3D-CM2P1B18X-2C_3P
LI1 LI3 = MURAT_DLW21SN670HQ2L_4P
LI2 LI5 LI6 LR2 LX2-LX6 = KC_WCM-2012HS-900T_4P
LT1 LT2 LX1 = KC_FBMA-L11-201209-221LMA30_2P
LT3 = CYNTE_PG031B-4R7MS_2P
PBATT1 = SUYIN_200028MR009G502ZL_9P
PC102 PC103 = C_6R3AVEA221M0645
PC201 = C_MP6VU330MC6
PC501 = C_ECST250ADA101MF611
PD1 PD2 = TVNST52302AB0_SOT523-3
PH1 PH500-PH503 PR1-PR11 PR13-PR21 PR26 PR100-PR106 PR112-PR116 PR201 PR204-PR208 PR210 PR300 PR302-PR305 PR307-PR309 PR400 PR402-PR404 PR409-PR412 PR500-PR505 PR507-PR510 PR514-PR516 PR520-PR527 PR529 PR530 PR533-PR535 PR538-PR543 PR701-PR706 PR708 PR710-PR712 PR714-PR719 PR722-PR729 R3-R8 R10 R13-R21 R121 R122 R376-R380 R432 R434 R488 R489 R696 R697 R926 R927 R1024 R1027-R1030 R1033 R1046-R1051 R1055 R1056 R1061 R1071-R1078 R1088 R1089 R2354 R2355 RA1-RA10 RA12 RA19 RA28 RA34 RA51 RA53 RA55 RA56 RA79-RA84 RA130 RA153-RA155 RA165 RA166 RA1109 RC1-RC71 RD3 RD6 RD7 RD14 RD15 RD17 RD18 RD45-RD53 RE1 RE3 RE5 RE7-RE21 RE36 RE43 RE47 RE49 RE50 RE60 RE71 RG1 RG2 RG5 RG6 RG8 RG10 RG11 RL27 RL31 RL33-RL36 RL38 RL40 RM11 RM13 RM110 RR1 RS6-RS9 RS09 RS10 RT2 RT3 RT12 RT14-RT22 RV31 RV32 RX1-RX9 RX12 RX18 RX21-RX24 RX26 RX33 RX36 = R_0402
PJPDC1 = ACES_50299-00501-003_5P
PL1 PL2 PL4 = TAIYO_FBMJ4516HS720NT_2P
PL3 = MURAT_BLM15BX102SN1D_2P
PL100 PL101 PL200 PL700 = L_7X7X3_M_2P
PL102 = L_5X5X3_M_2P
PL300 PL301 PL400 = TOKO_1239AS-H-1R0M-P2_2P
PL500 PL501 = PANAS_ETQP4LR15AFM_4P
PL502 = TAI-T_HCB2012KF-121T50_2P
PL701 = L_4X4X2_F_2P
PQ1 = FDV301N_NL_SOT23-3
PQ2 = RHU002N06_SOT323-3
PQ3 PQ4 PQ709 PQ710 PQ713 = 2N7002DW-T-R7_SOT363-6
PQ101 PQ102 PQ201 = MDV1528URH_PDFN33-8-5
PQ103 PQ104 PQ203 = MDV1527URH_POWERDFN33-8-5
PQ501 PQ503 = AON7934_DFN3X3A8-10
PQ701 PQ703 = MDS1525URH_SO8
PQ704 PQ706 = AO4407AL_SO8
PQ705 = SI4459ADY-T1-GE3_SO8
PQ707 = DTA144EUA_SC70-3
PQ708 PQ711 PQ712 = DTC115EUA_SC70-3
PR12 PR109-PR111 PR202 PR707 PR721 PR730 = R_1206
PR700 PR720 = R_1206_4P-D
PU100 = TPS51225CRUKR_QFN20_3X3
PU200 = RT8207MZQW_WQFN20_3X3
PU300 PU301 PU400 = SY8032ABC_SOT23-6
PU402 = APL5930KAI-TRG_SO8
PU500 = ISL95833HRTZ-T_TQFN32_4X4
PU700 = BQ24745RHDR_QFN28_5X5
Q8 Q50 Q70 Q71 Q2307 Q2308 QD18-QD20 QM30 = 2N7002K_SOT23-3
Q14 Q2309 QA5 QA6 QX6 = DMN66D0LDW-7_SOT363-6
Q57 Q58 QC1-QC4 = MESS138W-G_SOT323-3
QS2 = SI3456BDV-T1-E3_TSOP6
QS3 QX1 = 2N7002KW_SOT323-3
QX2 = SI3457CDV-T1-GE3_TSOP6
RC99 RC100 RD4 RD5 RE37 RE44 RT9 RT11 RX19 RX20 = R0402_0OHM
RD8 RD9 = R0402_0OHM: signal model: R0402_0OHM_0_0402_1%
RE4 RE6 RI1-RI6 RL28 RS11 RS12 RV299-RV301 = R_0805
RM25 RM26 RT1 = R0805_0OHM
RP15 RP36 RP54 RP56 RP63 RP65-RP68 = RP_0804_8P4R
RR2 RR3 = R_0402: signal model: R_0402_22_0402_5%
RV54 RV59 RX27 = R0603_0OHM
SW1 SW2 = SW_SMT1-05-A_4P
T94 T95 T97 T98 T100-T116 T192 T194-T196 T199-T204 T207 T209-T212 T215 T216 T218 T220 T221 = TPC12
TL1 = BOTH_NS0013LF_16P
U11 U59 = TPS22966DPUR_SON14_2X3
U54 U57 U61-U63 U65 U66 UC4 UC5 UC7 UC10 = SN74LVC1G07DCKR_SC70-5
U58 = FE1P1S-BQFN24B_WQFN24_4X4
U60 = AO4304L_SO8
U64 = G2129TL1U_SC70-6
UA1 = ALC3221-CG_MQFN48_6X6
UC8 = W25Q64DWSSIG_SO8
UD1 UX2 = MC74VHC1G08DFT2G_SC70-5
UE1 = KB9012QF-A2_LQFP128_14X14
UE2 = SN74LVC1G06DCKR_SC70-5
UE3 = G993P1UF_SOP8
UG1 = SLG3NB274VTR_TQFN16_2X3
UI1 UI4 UI5 UI7 = SY6288D20AAC_SOT23-5
UI2 UI3 UI6 = AP2301MPG-13_MSOP8
UL1 = RTL8106E-CG_QFN32_4X4
UL2 UX1 = APL3512ABI-TRG_SOT23-5
UL3 = SY6288C20AAC_SOT23-5
UR1 = RTS5179-GR_QFN24_4X4
USOC1 = FH8065301546401_FCBGA13_1170P
UT2 = RTD2132S-GR_QFN32_5X5
Y9 = Y_5YEA12000122IFA2Q3_4P
YC1 = Y_7V25000014_4P
YC2 = Y_Q13FC135000040_2P
YL2 = Y_FSX3M-25PM20FDO_4P

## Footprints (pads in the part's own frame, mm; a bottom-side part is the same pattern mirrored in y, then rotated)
2N7002DW-T-R7_SOT363-6
  oval 0.381x1.397 smd: 1(0,0) 2(0.65,0) 3(1.3,0) 4(1.3,1.725) 5(0.65,1.725) 6(0,1.725)
2N7002K_SOT23-3
  oval 1.016x1.524 smd: 1(0,0) 2(0.965,2.083) 3(-0.965,2.083)
2N7002KW_SOT323-3
  oval 0.813x0.914 smd: 1(0,0) 2(0.65,1.6) 3(-0.65,1.6)
ACES_50299-00501-003_5P
  round 1.803 hole 1.803 unplated: (-0.2,5.2) (8.2,5.2)
  oval 0.889x2.388 smd: 1(0,0) 2(2,0) 3(4,0) 4(6,0) 5(8,0)
ACES_85204-0300N_3P
  oval 0.787x1.6 smd: 1(0,0) 2(1.25,0) 3(2.5,0)
  rect 2.108x2.997 smd: 4(-2.55,-2.9) 5(5.05,-2.9)
ACES_88460-00601-P01_6P
  oval 0.508x0.991 smd: 1(0,0) 2(0.8,0) 3(1.6,0) 4(2.4,0) 5(3.2,0) 6(4,0)
  rect 1.194x1.702 smd: 7(-1.3,-1.95) 8(5.3,-1.95)
ACON_UARBG-4K1926_4P
  round 1.422 hole 0.914: 1(0,0) 2(-2.5,0) 3(-4.5,0) 4(-7,0)
  oval 1.397x2.819 hole 0.889x2.311: 5(-9.9,0) 6(2.9,0)
  oval 1.219x2.108 hole 0.711x1.6: 7(-11.2,-7.45) 8(4.2,-7.45)
ALC3221-CG_MQFN48_6X6
  oval 0.203x1.041 smd: 1(0,0) 2(0.4,0) 3(0.8,0) 4(1.2,0) 5(1.6,0) 6(2,0) 7(2.4,0) 8(2.8,0) 9(3.2,0) 10(3.6,0) 11(4,0) 12(4.4,0) 25(4.4,5.95) 26(4,5.95) 27(3.6,5.95) 28(3.2,5.95) 29(2.8,5.95) 30(2.4,5.95) 31(2,5.95) 32(1.6,5.95) 33(1.2,5.95) 34(0.8,5.95) 35(0.4,5.95) 36(0,5.95)
  oval 1.041x0.203 smd: 13(5.175,0.775) 14(5.175,1.175) 15(5.175,1.575) 16(5.175,1.975) 17(5.175,2.375) 18(5.175,2.775) 19(5.175,3.175) 20(5.175,3.575) 21(5.175,3.975) 22(5.175,4.375) 23(5.175,4.775) 24(5.175,5.175) 37(-0.775,5.175) 38(-0.775,4.775) 39(-0.775,4.375) 40(-0.775,3.975) 41(-0.775,3.575) 42(-0.775,3.175) 43(-0.775,2.775) 44(-0.775,2.375) 45(-0.775,1.975) 46(-0.775,1.575) 47(-0.775,1.175) 48(-0.775,0.775)
  rect 4.394x4.394 smd: 49(2.2,2.975)
AO4304L_SO8
  oval 0.635x1.854 smd: 1(0,0) 2(1.27,0) 3(2.54,0) 4(3.81,0) 5(3.81,5.165) 6(2.54,5.165) 7(1.27,5.165) 8(0,5.165)
AO4407AL_SO8
  oval 0.635x1.854 smd: 1(0,0) 2(1.27,0) 3(2.54,0) 4(3.81,0) 5(3.81,5.165) 6(2.54,5.165) 7(1.27,5.165) 8(0,5.165)
AON7934_DFN3X3A8-10
  oval 0.457x0.508 smd: 1(0,0) 2(0.65,0) 3(1.3,0) 4(1.95,0) 5(1.95,2.76) 6(1.3,2.76) 7(0.65,2.76) 8(0,2.76)
  rect 2.54x1.041 smd: 9(0.975,1.813)
  rect 2.54x0.559 smd: 10(0.975,0.708)
AP2301MPG-13_MSOP8
  oval 0.381x1.626 smd: 1(0,0) 2(0.65,0) 3(1.3,0) 4(1.95,0) 5(1.95,4.3) 6(1.3,4.3) 7(0.65,4.3) 8(0,4.3)
  rect 1.803x1.499 smd: 9(0.975,2.15)
APL3512ABI-TRG_SOT23-5
  oval 0.61x1.041 smd: 1(0,0) 2(0.95,0) 3(1.9,0) 4(1.9,2.7) 5(0,2.7)
APL5930KAI-TRG_SO8
  oval 0.635x1.854 smd: 1(0,0) 2(1.27,0) 3(2.54,0) 4(3.81,0) 5(3.81,5.165) 6(2.54,5.165) 7(1.27,5.165) 8(0,5.165)
  rect 2.87x2.489 smd: 9(1.905,2.582)
AZ5125-02SPR7G_SOT23-3
  oval 1.016x1.524 smd: 1(0,0) 2(0.965,2.083) 3(-0.965,2.083)
BAT54C-7-F_SOT23-3
  oval 1.016x1.524 smd: 1(0,0) 2(0.965,2.083) 3(-0.965,2.083)
BAV70W-7-F_SOT323-3
  oval 0.711x0.889 smd: 1(0,0) 2(-0.65,-1.9) 3(0.65,-1.9)
BOTH_NS0013LF_16P
  oval 0.762x1.905 smd: 1(0,0) 2(1.27,0) 3(2.54,0) 4(3.81,0) 5(5.08,0) 6(6.35,0) 7(7.62,0) 8(8.89,0) 9(8.89,8.8) 10(7.62,8.8) 11(6.35,8.8) 12(5.08,8.8) 13(3.81,8.8) 14(2.54,8.8) 15(1.27,8.8) 16(0,8.8)
BQ24745RHDR_QFN28_5X5
  oval 0.254x1.194 smd: 1(0,0) 2(0.5,0) 3(1,0) 4(1.5,0) 5(2.001,0) 6(2.501,0) 7(3.001,0) 15(3.001,4.8) 16(2.501,4.8) 17(2.001,4.8) 18(1.5,4.8) 19(1,4.8) 20(0.5,4.8) 21(0,4.8)
  oval 1.194x0.254 smd: 8(3.9,0.9) 9(3.9,1.4) 10(3.9,1.9) 11(3.9,2.4) 12(3.9,2.9) 13(3.9,3.4) 14(3.9,3.9) 22(-0.9,3.9) 23(-0.9,3.4) 24(-0.9,2.9) 25(-0.9,2.4) 26(-0.9,1.9) 27(-0.9,1.4) 28(-0.9,0.9)
  rect 2.692x2.692 smd: 29(1.5,2.4)
C_6R3AVEA221M0645
  oval 3.505x1.6 smd: 1(0,0) 2(-5.6,0)
C_0402
  rect 0.508x0.559 smd: 1(0,0) 2(0.914,0)
C_0603
  rect 0.635x0.889 smd: 1(0,0) 2(1.397,0)
C_0805
  rect 0.813x1.397 smd: 1(0,0) 2(1.702,0)
C_1206
  rect 1.016x1.651 smd: 1(0,0) 2(2.667,0)
C_D2
  rect 2.388x2.794 smd: 1(0,0) 2(6.4,0)
C_ECST250ADA101MF611
  oval 3.505x1.6 smd: 1(0,0) 2(-5.4,0)
C_MP6VLPS220MC4R2
  oval 3.505x1.6 smd: 1(0,0) 2(-5.6,0)
C_MP6VU330MC6
  oval 3.505x1.6 smd: 1(0,0) 2(5.6,0)
CHILI_NBQ100505T-800Y-N_2P
  rect 0.457x0.406 smd: 1(0,0) 2(0.85,0)
CONCR_525B01BE17A_52P
  round 1.6 hole 1.6 unplated: (-5.075,-4.85) (28.675,-4.85)
  oval 0.61x1.473 hole 0.406x0.711: 1(0,0) 3(0.8,0) 5(1.6,0) 7(2.4,0) 9(3.2,0) 11(4,0) 13(4.8,0) 15(5.6,0) 17(9.6,0) 19(10.4,0) 21(11.2,0) 23(12,0) 25(12.8,0) 27(13.6,0) 29(14.4,0) 31(15.2,0) 33(16,0) 35(16.8,0) 37(17.6,0) 39(18.4,0) 41(19.2,0) 43(20,0) 45(20.8,0) 47(21.6,0) 49(22.4,0) 51(23.2,0)
  oval 0.61x2.007 smd: 2(0.4,2.5) 4(1.2,2.5) 6(2,2.5) 8(2.8,2.5) 10(3.6,2.5) 12(4.4,2.5) 14(5.2,2.5) 16(6,2.5) 18(10,2.5) 20(10.8,2.5) 22(11.6,2.5) 24(12.4,2.5) 26(13.2,2.5) 28(14,2.5) 30(14.8,2.5) 32(15.6,2.5) 34(16.4,2.5) 36(17.2,2.5) 38(18,2.5) 40(18.8,2.5) 42(19.6,2.5) 44(20.4,2.5) 46(21.2,2.5) 48(22,2.5) 50(22.8,2.5) 52(23.6,2.5)
  oval 1.549x2.769 hole 0.787x2.007: 53(28.675,-7.65) 54(-5.075,-7.65)
CYNTE_PG031B-4R7MS_2P
  rect 0.889x1.194 smd: 1(0,0) 2(2.2,0)
DMN66D0LDW-7_SOT363-6
  oval 0.432x0.61 smd: 1(0,0) 2(0.65,0) 3(1.3,0) 4(1.3,1.9) 5(0.65,1.9) 6(0,1.9)
DTA144EUA_SC70-3
  rect 0.813x0.914 smd: 1(0,0) 2(0.65,1.6) 3(-0.65,1.6)
DTC115EUA_SC70-3
  oval 0.813x0.914 smd: 1(0,0) 2(0.65,1.6) 3(-0.65,1.6)
E-T_3703-Q04N-11R_4P
  oval 0.61x1.549 smd: 1(0,0) 2(1,0) 3(2,0) 4(3,0)
  rect 1.194x2.007 smd: 5(4.3,-3.775) 6(-1.3,-3.775)
F_1206L150PR
  rect 0.991x1.803 smd: 1(0,0) 2(2.8,0)
FDV301N_NL_SOT23-3
  oval 1.016x1.524 smd: 1(0,0) 2(0.965,2.083) 3(-0.965,2.083)
FE1P1S-BQFN24B_WQFN24_4X4
  oval 0.254x0.965 smd: 1(0,0) 2(0.5,0) 3(1,0) 4(1.5,0) 5(2,0) 6(2.5,0) 13(2.5,4.026) 14(2,4.026) 15(1.5,4.026) 16(1,4.026) 17(0.5,4.026) 18(0,4.026)
  oval 0.965x0.254 smd: 7(3.263,0.763) 8(3.263,1.263) 9(3.263,1.763) 10(3.263,2.263) 11(3.263,2.763) 12(3.263,3.263) 19(-0.763,3.263) 20(-0.763,2.763) 21(-0.763,2.263) 22(-0.763,1.763) 23(-0.763,1.263) 24(-0.763,0.763)
  rect 2.794x2.794 smd: 25(1.25,2.013)
FH8065301546401_FCBGA13_1170P
  round 0.521 smd: A3(-0.863,0) A52(-25.197,0) B2(-0.431,0.431) B53(-25.628,0.431) BH1(0,23.197) BH53(-25.628,23.197) BJ2(-0.431,23.628) BJ52(-25.197,23.628) C1(0,0.863)
  round 0.406 smd: A5(-1.644,0) A6(-2.368,0) A49(-23.806,0) A51(-24.587,0) B52(-25.039,0.589) BE1(0,21.806) BE53(-25.628,21.806) BG1(0,22.587) BG53(-25.628,22.587) BH2(-0.589,23.039) BH52(-25.039,23.039) BJ3(-1.041,23.628) BJ5(-1.822,23.628) BJ49(-23.806,23.628) BJ51(-24.587,23.628) C53(-25.628,1.041) E1(0,1.644) E53(-25.628,1.822) F1(0,2.368)
  round 0.356 smd: A7(-3.066,0) A9(-3.978,0) A47(-22.435,0) A48(-23.108,0) B4(-1.182,0.576) B5(-1.776,0.592) B6(-2.369,0.593) B8(-3.556,0.59) B46(-22.072,0.59) B48(-23.259,0.593) B49(-23.852,0.592) B50(-24.446,0.576) BC1(0,20.435) BC2(-0.568,20.666) BC52(-25.06,20.666) BC53(-25.628,20.435) BD1(0,21.108) BD2(-0.593,21.259) BD52(-25.035,21.259) BD53(-25.628,21.108) BE2(-0.592,21.852) BE52(-25.037,21.852) BF2(-0.576,22.446) BF52(-25.052,22.446) BG3(-1.17,22.458) BG51(-24.458,22.458) BH4(-1.182,23.052) BH5(-1.776,23.037) BH6(-2.369,23.035) BH8(-3.556,23.038) BH46(-22.072,23.038) BH48(-23.259,23.035) BH49(-23.852,23.037) BH50(-24.446,23.052) BJ6(-2.52,23.628) BJ7(-3.194,23.628) BJ47(-22.435,23.628) BJ48(-23.108,23.628) C3(-1.17,1.17) C51(-24.458,1.17) D2(-0.576,1.182) D52(-25.052,1.182) E2(-0.592,1.776) E52(-25.037,1.776) F2(-0.593,2.369) F52(-25.035,2.369) F53(-25.628,2.52) G1(0,3.135) G2(-0.568,2.962) G52(-25.06,2.962) G53(-25.628,3.194) J1(0,3.998)
  oval 0.254x0.343 smd: A11(-5.04,0) A13(-6.011,0) A15(-6.983,0) A17(-7.955,0) A19(-8.927,0) A21(-9.899,0) A23(-10.87,0) A25(-11.842,0) A27(-12.814,0) A29(-13.786,0) A31(-14.758,0) A33(-15.729,0) A35(-16.701,0) A37(-17.673,0) A39(-18.645,0) A41(-19.617,0) A43(-20.588,0) A45(-21.56,0) BJ9(-4.068,23.628) BJ11(-5.04,23.628) BJ13(-6.011,23.628) BJ15(-6.983,23.628) BJ17(-7.955,23.628) BJ19(-8.927,23.628) BJ21(-9.899,23.628) BJ23(-10.87,23.628) BJ25(-11.842,23.628) BJ27(-12.814,23.628) BJ29(-13.786,23.628) BJ31(-14.758,23.628) BJ33(-15.729,23.628) BJ35(-16.701,23.628) BJ37(-17.673,23.628) BJ39(-18.645,23.628) BJ41(-19.617,23.628) BJ43(-20.588,23.628) BJ45(-21.56,23.628)
  oval 0.343x0.254 smd: AA1(0,9.87) AA53(-25.628,9.87) AC1(0,10.842) AC53(-25.628,10.842) AE1(0,11.814) AE53(-25.628,11.814) AG1(0,12.786) AG53(-25.628,12.786) AJ1(0,13.758) AJ53(-25.628,13.758) AL1(0,14.729) AL53(-25.628,14.729) AN1(0,15.701) AN53(-25.628,15.701) AR1(0,16.673) AR53(-25.628,16.673) AU1(0,17.645) AU53(-25.628,17.645) AW1(0,18.617) AW53(-25.628,18.617) BA1(0,19.588) BA53(-25.628,19.588) J53(-25.628,4.04) L1(0,5.011) L53(-25.628,5.011) N1(0,5.983) N53(-25.628,5.983) R1(0,6.955) R53(-25.628,6.955) U1(0,7.927) U53(-25.628,7.927) W1(0,8.899) W53(-25.628,8.899)
  round 0.279 smd: AA3(-0.743,9.87) AA51(-24.885,9.87) AB2(-0.385,10.356) AB3(-1.084,10.356) AB51(-24.544,10.356) AB52(-25.243,10.356) AC3(-0.743,10.842) AC51(-24.885,10.842) AD2(-0.385,11.328) AD3(-1.099,11.334) AD51(-24.529,11.334) AD52(-25.243,11.328) AE3(-0.743,11.814) AE4(-1.448,11.814) AE50(-24.18,11.814) AE51(-24.885,11.814) AF2(-0.385,12.3) AF3(-1.099,12.294) AF51(-24.529,12.294) AF52(-25.243,12.3) AG3(-0.743,12.786) AG51(-24.885,12.786) AH2(-0.385,13.272) AH3(-1.084,13.272) AH51(-24.544,13.272) AH52(-25.243,13.272) AJ3(-0.743,13.758) AJ51(-24.885,13.758) AK2(-0.385,14.244) AK3(-1.084,14.244) AK51(-24.544,14.244) AK52(-25.243,14.244) AL3(-0.743,14.729) AL51(-24.885,14.729) AM2(-0.385,15.215) AM3(-1.084,15.215) AM51(-24.544,15.215) AM52(-25.243,15.215) AN3(-0.743,15.701) AN51(-24.885,15.701) AP2(-0.385,16.187) AP3(-1.084,16.187) AP51(-24.544,16.187) AP52(-25.243,16.187) AR3(-0.743,16.673) AR51(-24.885,16.673) AT2(-0.385,17.159) AT3(-1.084,17.159) AT51(-24.544,17.159) AT52(-25.243,17.159) AU3(-0.743,17.645) AU51(-24.885,17.645) AV2(-0.385,18.131) AV3(-1.084,18.131) AV51(-24.544,18.131) AV52(-25.243,18.131) AW3(-0.743,18.617) AW51(-24.885,18.617) AY2(-0.385,19.103) AY3(-1.084,19.103) AY51(-24.544,19.103) AY52(-25.243,19.103) B10(-4.554,0.385) B12(-5.526,0.385) B14(-6.497,0.385) B16(-7.469,0.385) B18(-8.441,0.385) B20(-9.413,0.385) B22(-10.385,0.385) B24(-11.356,0.385) B26(-12.328,0.385) B28(-13.3,0.385) B30(-14.272,0.385) B32(-15.244,0.385) B34(-16.215,0.385) B36(-17.187,0.385) B38(-18.159,0.385) B40(-19.131,0.385) B42(-20.103,0.385) B44(-21.074,0.385) BA3(-0.743,19.588) BA51(-24.885,19.588) BB3(-0.885,20.165) BB51(-24.743,20.165) BF27(-12.814,22.18) BG9(-4.116,22.842) BG11(-5.04,22.885) BG12(-5.526,22.544) BG13(-6.011,22.885) BG14(-6.497,22.544) BG15(-6.983,22.885) BG16(-7.469,22.544) BG17(-7.955,22.885) BG18(-8.441,22.544) BG19(-8.927,22.885) BG20(-9.413,22.544) BG21(-9.899,22.885) BG22(-10.385,22.544) BG23(-10.87,22.885) BG24(-11.356,22.544) BG25(-11.842,22.885) BG26(-12.334,22.529) BG27(-12.814,22.885) BG28(-13.294,22.529) BG29(-13.786,22.885) BG30(-14.272,22.544) BG31(-14.758,22.885) BG32(-15.244,22.544) BG33(-15.729,22.885) BG34(-16.215,22.544) BG35(-16.701,22.885) BG36(-17.187,22.544) BG37(-17.673,22.885) BG38(-18.159,22.544) BG39(-18.645,22.885) BG40(-19.131,22.544) BG41(-19.617,22.885) BG42(-20.103,22.544) BG43(-20.588,22.885) BG45(-21.512,22.842) BH10(-4.554,23.243) BH12(-5.526,23.243) BH14(-6.497,23.243) BH16(-7.469,23.243) BH18(-8.441,23.243) BH20(-9.413,23.243) BH22(-10.385,23.243) BH24(-11.356,23.243) BH26(-12.328,23.243) BH28(-13.3,23.243) BH30(-14.272,23.243) BH32(-15.244,23.243) BH34(-16.215,23.243) BH36(-17.187,23.243) BH38(-18.159,23.243) BH40(-19.131,23.243) BH42(-20.103,23.243) BH44(-21.074,23.243) C9(-4.116,0.786) C11(-5.04,0.743) C12(-5.526,1.084) C13(-6.011,0.743) C14(-6.497,1.084) C15(-6.983,0.743) C16(-7.469,1.084) C17(-7.955,0.743) C18(-8.441,1.084) C19(-8.927,0.743) C20(-9.413,1.084) C21(-9.899,0.743) C22(-10.385,1.084) C23(-10.87,0.743) C24(-11.356,1.084) C25(-11.842,0.743) C26(-12.334,1.099) C27(-12.814,0.743) C28(-13.294,1.099) C29(-13.786,0.743) C30(-14.272,1.084) C31(-14.758,0.743) C32(-15.244,1.084) C33(-15.729,0.743) C34(-16.215,1.084) C35(-16.701,0.743) C36(-17.187,1.084) C37(-17.673,0.743) C38(-18.159,1.084) C39(-18.645,0.743) C40(-19.131,1.084) C41(-19.617,0.743) C42(-20.103,1.084) C43(-20.588,0.743) C45(-21.512,0.786) D27(-12.814,1.448) H3(-0.885,3.463) H51(-24.743,3.463) J3(-0.743,4.04) J51(-24.885,4.04) K2(-0.385,4.526) K3(-1.084,4.526) K51(-24.544,4.526) K52(-25.243,4.526) L3(-0.743,5.011) L51(-24.885,5.011) M2(-0.385,5.497) M3(-1.084,5.497) M51(-24.544,5.497) M52(-25.243,5.497) N3(-0.743,5.983) N51(-24.885,5.983) P2(-0.385,6.469) P3(-1.084,6.469) P51(-24.544,6.469) P52(-25.243,6.469) R3(-0.743,6.955) R51(-24.885,6.955) T2(-0.385,7.441) T3(-1.084,7.441) T51(-24.544,7.441) T52(-25.243,7.441) U3(-0.743,7.927) U51(-24.885,7.927) V2(-0.385,8.413) V3(-1.084,8.413) V51(-24.544,8.413) V52(-25.243,8.413) W3(-0.743,8.899) W51(-24.885,8.899) Y2(-0.385,9.385) Y3(-1.084,9.385) Y51(-24.544,9.385) Y52(-25.243,9.385)
  round 0.33 smd: AA16(-7.507,9.853) AA18(-8.265,9.853) AA19(-9.023,9.853) AA21(-9.781,9.853) AA22(-10.539,9.853) AA24(-11.298,9.853) AA25(-12.056,9.853) AA27(-12.814,9.853) AA29(-13.572,9.853) AA30(-14.33,9.853) AA32(-15.089,9.853) AA33(-15.847,9.853) AA35(-16.605,9.853) AA36(-17.363,9.853) AA38(-18.121,9.853) AC16(-7.507,10.638) AC18(-8.265,10.638) AC19(-9.023,10.638) AC21(-9.781,10.638) AC22(-10.539,10.638) AC24(-11.298,10.638) AC25(-12.056,10.638) AC27(-12.814,10.638) AC29(-13.572,10.638) AC30(-14.33,10.638) AC32(-15.089,10.638) AC33(-15.847,10.638) AC35(-16.605,10.638) AC36(-17.363,10.638) AC38(-18.121,10.638) AD16(-7.507,11.422) AD18(-8.265,11.422) AD19(-9.023,11.422) AD21(-9.781,11.422) AD22(-10.539,11.422) AD24(-11.298,11.422) AD25(-12.056,11.422) AD27(-12.814,11.422) AD29(-13.572,11.422) AD30(-14.33,11.422) AD32(-15.089,11.422) AD33(-15.847,11.422) AD35(-16.605,11.422) AD36(-17.363,11.422) AD38(-18.121,11.422) AF16(-7.507,12.206) AF18(-8.265,12.206) AF19(-9.023,12.206) AF21(-9.781,12.206) AF22(-10.539,12.206) AF24(-11.298,12.206) AF25(-12.056,12.206) AF27(-12.814,12.206) AF29(-13.572,12.206) AF30(-14.33,12.206) AF32(-15.089,12.206) AF33(-15.847,12.206) AF35(-16.605,12.206) AF36(-17.363,12.206) AF38(-18.121,12.206) AG16(-7.507,12.991) AG18(-8.265,12.991) AG19(-9.023,12.991) AG21(-9.781,12.991) AG22(-10.539,12.991) AG24(-11.298,12.991) AG25(-12.056,12.991) AG27(-12.814,12.991) AG29(-13.572,12.991) AG30(-14.33,12.991) AG32(-15.089,12.991) AG33(-15.847,12.991) AG35(-16.605,12.991) AG36(-17.363,12.991) AG38(-18.121,12.991) AJ16(-7.507,13.775) AJ18(-8.265,13.775) AJ19(-9.023,13.775) AJ21(-9.781,13.775) AJ22(-10.539,13.775) AJ24(-11.298,13.775) AJ25(-12.056,13.775) AJ27(-12.814,13.775) AJ29(-13.572,13.775) AJ30(-14.33,13.775) AJ32(-15.089,13.775) AJ33(-15.847,13.775) AJ35(-16.605,13.775) AJ36(-17.363,13.775) AJ38(-18.121,13.775) AK16(-7.507,14.559) AK18(-8.265,14.559) AK19(-9.023,14.559) AK21(-9.781,14.559) AK22(-10.539,14.559) AK24(-11.298,14.559) AK25(-12.056,14.559) AK27(-12.814,14.559) AK29(-13.572,14.559) AK30(-14.33,14.559) AK32(-15.089,14.559) AK33(-15.847,14.559) AK35(-16.605,14.559) AK36(-17.363,14.559) AK38(-18.121,14.559) AM16(-7.507,15.344) AM18(-8.265,15.344) AM19(-9.023,15.344) AM21(-9.781,15.344) AM22(-10.539,15.344) AM24(-11.298,15.344) AM25(-12.056,15.344) AM27(-12.814,15.344) AM29(-13.572,15.344) AM30(-14.33,15.344) AM32(-15.089,15.344) AM33(-15.847,15.344) AM35(-16.605,15.344) AM36(-17.363,15.344) AM38(-18.121,15.344) AN16(-7.507,16.128) AN18(-8.265,16.128) AN19(-9.023,16.128) AN21(-9.781,16.128) AN22(-10.539,16.128) AN24(-11.298,16.128) AN25(-12.056,16.128) AN27(-12.814,16.128) AN29(-13.572,16.128) AN30(-14.33,16.128) AN32(-15.089,16.128) AN33(-15.847,16.128) AN35(-16.605,16.128) AN36(-17.363,16.128) AN38(-18.121,16.128) U16(-7.507,7.5) U18(-8.265,7.5) U19(-9.023,7.5) U21(-9.781,7.5) U22(-10.539,7.5) U24(-11.298,7.5) U25(-12.056,7.5) U27(-12.814,7.5) U29(-13.572,7.5) U30(-14.33,7.5) U32(-15.089,7.5) U33(-15.847,7.5) U35(-16.605,7.5) U36(-17.363,7.5) U38(-18.121,7.5) V16(-7.507,8.284) V18(-8.265,8.284) V19(-9.023,8.284) V21(-9.781,8.284) V22(-10.539,8.284) V24(-11.298,8.284) V25(-12.056,8.284) V27(-12.814,8.284) V29(-13.572,8.284) V30(-14.33,8.284) V32(-15.089,8.284) V33(-15.847,8.284) V35(-16.605,8.284) V36(-17.363,8.284) V38(-18.121,8.284) Y16(-7.507,9.069) Y18(-8.265,9.069) Y19(-9.023,9.069) Y21(-9.781,9.069) Y22(-10.539,9.069) Y24(-11.298,9.069) Y25(-12.056,9.069) Y27(-12.814,9.069) Y29(-13.572,9.069) Y30(-14.33,9.069) Y32(-15.089,9.069) Y33(-15.847,9.069) Y35(-16.605,9.069) Y36(-17.363,9.069) Y38(-18.121,9.069)
  round 0.305 smd: AB4(-1.677,10.366) AB6(-2.351,10.366) AB7(-3.062,10.366) AB9(-3.773,10.366) AB10(-4.484,10.366) AB12(-5.196,10.366) AB13(-5.907,10.366) AB14(-6.618,10.366) AB40(-19.01,10.366) AB41(-19.721,10.366) AB42(-20.433,10.366) AB44(-21.144,10.366) AB45(-21.855,10.366) AB47(-22.566,10.366) AB48(-23.277,10.366) AB50(-23.951,10.366) AD4(-1.819,11.351) AD6(-2.41,11.289) AD7(-3.062,11.339) AD9(-3.773,11.339) AD10(-4.484,11.339) AD12(-5.196,11.339) AD13(-5.907,11.339) AD14(-6.618,11.339) AD40(-19.01,11.339) AD41(-19.721,11.339) AD42(-20.433,11.339) AD44(-21.144,11.339) AD45(-21.855,11.339) AD47(-22.566,11.339) AD48(-23.218,11.289) AD50(-23.809,11.351) AE6(-2.706,11.814) AE8(-3.418,11.814) AE9(-4.129,11.814) AE11(-4.84,11.814) AE12(-5.551,11.814) AE14(-6.262,11.814) AE40(-19.366,11.814) AE42(-20.077,11.814) AE43(-20.788,11.814) AE45(-21.499,11.814) AE46(-22.211,11.814) AE48(-22.922,11.814) AF4(-1.819,12.277) AF6(-2.41,12.339) AF7(-3.062,12.289) AF9(-3.773,12.289) AF10(-4.484,12.289) AF12(-5.196,12.289) AF13(-5.907,12.289) AF14(-6.618,12.289) AF40(-19.01,12.289) AF41(-19.721,12.289) AF42(-20.433,12.289) AF44(-21.144,12.289) AF45(-21.855,12.289) AF47(-22.566,12.289) AF48(-23.218,12.339) AF50(-23.809,12.277) AH4(-1.677,13.262) AH6(-2.351,13.262) AH7(-3.062,13.262) AH9(-3.773,13.262) AH10(-4.484,13.262) AH12(-5.196,13.262) AH13(-5.907,13.262) AH14(-6.618,13.262) AH40(-19.01,13.262) AH41(-19.721,13.262) AH42(-20.433,13.262) AH44(-21.144,13.262) AH45(-21.855,13.262) AH47(-22.566,13.262) AH48(-23.277,13.262) AH50(-23.951,13.262) AK4(-1.677,14.253) AK6(-2.351,14.253) AK7(-3.062,14.253) AK9(-3.773,14.253) AK10(-4.484,14.253) AK12(-5.196,14.253) AK13(-5.907,14.253) AK14(-6.618,14.253) AK40(-19.01,14.253) AK41(-19.721,14.253) AK42(-20.433,14.253) AK44(-21.144,14.253) AK45(-21.855,14.253) AK47(-22.566,14.253) AK48(-23.277,14.253) AK50(-23.951,14.253) AM4(-1.677,15.2) AM6(-2.351,15.226) AM7(-3.062,15.226) AM9(-3.773,15.226) AM10(-4.484,15.226) AM12(-5.196,15.226) AM13(-5.907,15.226) AM14(-6.618,15.226) AM40(-19.01,15.226) AM41(-19.721,15.226) AM42(-20.433,15.226) AM44(-21.144,15.226) AM45(-21.855,15.226) AM47(-22.566,15.226) AM48(-23.277,15.226) AM50(-23.951,15.2) AN5(-1.995,15.701) AN6(-2.706,15.701) AN8(-3.418,15.701) AN9(-4.129,15.701) AN11(-4.84,15.701) AN12(-5.551,15.701) AN14(-6.262,15.701) AN40(-19.366,15.701) AN42(-20.077,15.701) AN43(-20.788,15.701) AN45(-21.499,15.701) AN46(-22.211,15.701) AN48(-22.922,15.701) AN49(-23.633,15.701) AP4(-1.677,16.202) AP6(-2.351,16.176) AP7(-3.062,16.176) AP9(-3.773,16.176) AP10(-4.484,16.176) AP12(-5.196,16.176) AP13(-5.907,16.176) AP14(-6.618,16.176) AP40(-19.01,16.176) AP41(-19.721,16.176) AP42(-20.433,16.176) AP44(-21.144,16.176) AP45(-21.855,16.176) AP47(-22.566,16.176) AP48(-23.277,16.176) AP50(-23.951,16.202) AT4(-1.677,17.15) AT6(-2.351,17.15) AT7(-3.062,17.15) AT9(-3.773,17.15) AT10(-4.484,17.15) AT12(-5.196,17.15) AT13(-5.907,17.15) AT14(-6.509,17.15) AT16(-7.479,17.01) AT18(-8.452,17.01) AT19(-8.927,17.366) AT20(-9.402,17.01) AT22(-10.375,17.01) AT24(-11.366,17.01) AT26(-12.339,17.01) AT27(-12.814,17.366) AT28(-13.289,17.01) AT30(-14.262,17.01) AT32(-15.253,17.01) AT34(-16.226,17.01) AT35(-16.701,17.366) AT36(-17.176,17.01) AT38(-18.15,17.01) AT40(-19.119,17.15) AT41(-19.721,17.15) AT42(-20.433,17.15) AT44(-21.144,17.15) AT45(-21.855,17.15) AT47(-22.566,17.15) AT48(-23.277,17.15) AT50(-23.951,17.15) AU16(-7.479,17.721) AU18(-8.452,17.721) AU20(-9.402,17.721) AU22(-10.375,17.721) AU24(-11.366,17.721) AU26(-12.339,17.721) AU28(-13.289,17.721) AU30(-14.262,17.721) AU32(-15.253,17.721) AU34(-16.226,17.721) AU36(-17.176,17.721) AU38(-18.15,17.721) AV4(-1.677,18.14) AV6(-2.351,18.14) AV7(-3.062,18.14) AV9(-3.773,18.14) AV10(-4.484,18.14) AV12(-5.196,18.14) AV13(-5.907,18.14) AV14(-6.488,18.26) AV16(-7.479,18.433) AV18(-8.452,18.433) AV19(-8.927,18.077) AV20(-9.402,18.433) AV22(-10.375,18.433) AV24(-11.366,18.433) AV26(-12.339,18.433) AV27(-12.814,18.077) AV28(-13.289,18.433) AV30(-14.262,18.433) AV32(-15.253,18.433) AV34(-16.226,18.433) AV35(-16.701,18.077) AV36(-17.176,18.433) AV38(-18.15,18.433) AV40(-19.14,18.26) AV41(-19.721,18.14) AV42(-20.433,18.14) AV44(-21.144,18.14) AV45(-21.855,18.14) AV47(-22.566,18.14) AV48(-23.277,18.14) AV50(-23.951,18.14) AW13(-6.063,18.729) AW19(-8.927,18.788) AW27(-12.814,18.788) AW35(-16.701,18.788) AW41(-19.565,18.729) AY4(-1.677,19.131) AY6(-2.351,19.131) AY7(-3.062,19.131) AY9(-3.773,19.131) AY10(-4.484,19.131) AY12(-5.497,19.154) AY14(-6.488,19.144) AY16(-7.479,19.144) AY18(-8.452,19.144) AY20(-9.402,19.144) AY22(-10.375,19.144) AY24(-11.366,19.144) AY26(-12.339,19.144) AY28(-13.289,19.144) AY30(-14.262,19.144) AY32(-15.253,19.144) AY34(-16.226,19.144) AY36(-17.176,19.144) AY38(-18.15,19.144) AY40(-19.14,19.144) AY42(-20.131,19.154) AY44(-21.144,19.131) AY45(-21.855,19.131) AY47(-22.566,19.131) AY48(-23.277,19.131) AY50(-23.951,19.131) B7(-2.962,0.584) B47(-22.666,0.584) BA12(-5.497,19.855) BA14(-6.488,19.855) BA16(-7.479,19.855) BA18(-8.452,19.855) BA19(-8.927,19.499) BA20(-9.402,19.855) BA22(-10.375,19.855) BA24(-11.366,19.855) BA26(-12.339,19.855) BA27(-12.814,19.499) BA28(-13.289,19.855) BA30(-14.262,19.855) BA32(-15.253,19.855) BA34(-16.226,19.855) BA35(-16.701,19.499) BA36(-17.176,19.855) BA38(-18.15,19.855) BA40(-19.14,19.855) BA42(-20.131,19.855) BB4(-1.556,20.121) BB5(-2.267,20.121) BB7(-2.979,20.121) BB8(-3.69,20.121) BB10(-4.507,19.984) BB19(-8.927,20.211) BB27(-12.814,20.211) BB35(-16.701,20.211) BB44(-21.121,19.984) BB46(-21.938,20.121) BB47(-22.649,20.121) BB49(-23.361,20.121) BB50(-24.072,20.121) BC10(-4.507,20.578) BC12(-5.497,20.566) BC14(-6.488,20.566) BC16(-7.479,20.566) BC18(-8.452,20.566) BC20(-9.402,20.566) BC22(-10.375,20.566) BC24(-11.366,20.566) BC26(-12.339,20.566) BC28(-13.289,20.566) BC30(-14.262,20.566) BC32(-15.253,20.566) BC34(-16.226,20.566) BC36(-17.176,20.566) BC38(-18.15,20.566) BC40(-19.14,20.566) BC42(-20.131,20.566) BC44(-21.121,20.578) BD5(-2.249,21.116) BD7(-3.102,21.116) BD10(-4.507,21.271) BD12(-5.497,21.277) BD14(-6.488,21.277) BD16(-7.479,21.277) BD18(-8.452,21.277) BD19(-8.927,20.922) BD20(-9.402,21.277) BD22(-10.375,21.277) BD24(-11.366,21.277) BD26(-12.289,21.218) BD27(-12.814,20.922) BD28(-13.339,21.218) BD30(-14.262,21.277) BD32(-15.253,21.277) BD34(-16.226,21.277) BD35(-16.701,20.922) BD36(-17.176,21.277) BD38(-18.15,21.277) BD40(-19.14,21.277) BD42(-20.131,21.277) BD44(-21.121,21.271) BD47(-22.526,21.116) BD49(-23.379,21.116) BE3(-1.171,21.394) BE8(-3.494,21.561) BE19(-8.927,21.633) BE35(-16.701,21.633) BE46(-22.134,21.561) BE51(-24.457,21.394) BF4(-1.651,21.977) BF6(-2.701,22.053) BF10(-4.507,21.982) BF12(-5.497,21.951) BF14(-6.488,21.951) BF16(-7.479,21.951) BF18(-8.426,21.951) BF20(-9.428,21.951) BF22(-10.375,21.951) BF24(-11.366,21.951) BF26(-12.351,21.809) BF28(-13.277,21.809) BF30(-14.262,21.951) BF32(-15.253,21.951) BF34(-16.2,21.951) BF36(-17.202,21.951) BF38(-18.15,21.951) BF40(-19.14,21.951) BF42(-20.131,21.951) BF44(-21.121,21.982) BF48(-22.927,22.053) BF50(-23.977,21.977) BG5(-2.234,22.457) BG7(-3.261,22.523) BG47(-22.367,22.523) BG49(-23.394,22.457) BH7(-2.962,23.044) BH47(-22.666,23.044) C5(-2.234,1.171) C7(-3.261,1.105) C47(-22.367,1.105) C49(-23.394,1.171) D4(-1.651,1.651) D6(-2.701,1.576) D10(-4.507,1.646) D12(-5.497,1.677) D14(-6.488,1.677) D16(-7.479,1.677) D18(-8.426,1.677) D20(-9.428,1.677) D22(-10.375,1.677) D24(-11.366,1.677) D26(-12.351,1.819) D28(-13.277,1.819) D30(-14.262,1.677) D32(-15.253,1.677) D34(-16.2,1.677) D36(-17.202,1.677) D38(-18.15,1.677) D40(-19.14,1.677) D42(-20.131,1.677) D44(-21.121,1.646) D48(-22.927,1.576) D50(-23.977,1.651) E3(-1.171,2.234) E8(-3.494,2.067) E19(-8.927,1.995) E35(-16.701,1.995) E46(-22.134,2.067) E51(-24.457,2.234) F5(-2.249,2.512) F7(-3.102,2.512) F10(-4.507,2.357) F12(-5.497,2.351) F14(-6.488,2.351) F16(-7.479,2.351) F18(-8.452,2.351) F19(-8.927,2.706) F20(-9.402,2.351) F22(-10.375,2.351) F24(-11.366,2.351) F26(-12.289,2.41) F27(-12.814,2.706) F28(-13.339,2.41) F30(-14.262,2.351) F32(-15.253,2.351) F34(-16.226,2.351) F35(-16.701,2.706) F36(-17.176,2.351) F38(-18.15,2.351) F40(-19.14,2.351) F42(-20.131,2.351) F44(-21.121,2.357) F47(-22.526,2.512) F49(-23.379,2.512) G10(-4.507,3.05) G12(-5.497,3.062) G14(-6.488,3.062) G16(-7.479,3.062) G18(-8.452,3.062) G20(-9.402,3.062) G22(-10.375,3.062) G24(-11.366,3.062) G26(-12.339,3.062) G28(-13.289,3.062) G30(-14.262,3.062) G32(-15.253,3.062) G34(-16.226,3.062) G36(-17.176,3.062) G38(-18.15,3.062) G40(-19.14,3.062) G42(-20.131,3.062) G44(-21.121,3.05) H4(-1.556,3.507) H5(-2.267,3.507) H7(-2.979,3.507) H8(-3.69,3.507) H10(-4.507,3.644) H19(-8.927,3.418) H27(-12.814,3.418) H35(-16.701,3.418) H44(-21.121,3.644) H46(-21.938,3.507) H47(-22.649,3.507) H49(-23.361,3.507) H50(-24.072,3.507) J12(-5.497,3.773) J14(-6.488,3.773) J16(-7.479,3.773) J18(-8.452,3.773) J19(-8.927,4.129) J20(-9.402,3.773) J22(-10.375,3.773) J24(-11.366,3.773) J26(-12.339,3.773) J27(-12.814,4.129) J28(-13.289,3.773) J30(-14.262,3.773) J32(-15.253,3.773) J34(-16.226,3.773) J35(-16.701,4.129) J36(-17.176,3.773) J38(-18.15,3.773) J40(-19.14,3.773) J42(-20.131,3.773) K4(-1.677,4.497) K6(-2.351,4.497) K7(-3.062,4.497) K9(-3.773,4.497) K10(-4.484,4.497) K12(-5.497,4.474) K14(-6.488,4.484) K16(-7.479,4.484) K18(-8.452,4.484) K20(-9.402,4.484) K22(-10.375,4.484) K24(-11.366,4.484) K26(-12.339,4.484) K28(-13.289,4.484) K30(-14.262,4.484) K32(-15.253,4.484) K34(-16.226,4.484) K36(-17.176,4.484) K38(-18.15,4.484) K40(-19.14,4.484) K42(-20.131,4.474) K44(-21.144,4.497) K45(-21.855,4.497) K47(-22.566,4.497) K48(-23.277,4.497) K50(-23.951,4.497) L13(-6.063,4.899) L19(-8.927,4.84) L27(-12.814,4.84) L35(-16.701,4.84) L41(-19.565,4.899) M4(-1.677,5.488) M6(-2.351,5.488) M7(-3.062,5.488) M9(-3.773,5.488) M10(-4.484,5.488) M12(-5.196,5.488) M13(-5.907,5.488) M14(-6.488,5.368) M16(-7.479,5.196) M18(-8.452,5.196) M19(-8.927,5.551) M20(-9.402,5.196) M22(-10.375,5.196) M24(-11.366,5.196) M26(-12.339,5.196) M27(-12.814,5.551) M28(-13.289,5.196) M30(-14.262,5.196) M32(-15.253,5.196) M34(-16.226,5.196) M35(-16.701,5.551) M36(-17.176,5.196) M38(-18.15,5.196) M40(-19.14,5.368) M41(-19.721,5.488) M42(-20.433,5.488) M44(-21.144,5.488) M45(-21.855,5.488) M47(-22.566,5.488) M48(-23.277,5.488) M50(-23.951,5.488) N16(-7.479,5.907) N18(-8.452,5.907) N20(-9.402,5.907) N22(-10.375,5.907) N24(-11.366,5.907) N26(-12.339,5.907) N28(-13.289,5.907) N30(-14.262,5.907) N32(-15.253,5.907) N34(-16.226,5.907) N36(-17.176,5.907) N38(-18.15,5.907) P4(-1.677,6.479) P6(-2.351,6.479) P7(-3.062,6.479) P9(-3.773,6.479) P10(-4.484,6.479) P12(-5.196,6.479) P13(-5.907,6.479) P14(-6.509,6.479) P16(-7.479,6.618) P18(-8.452,6.618) P19(-8.927,6.262) P20(-9.402,6.618) P22(-10.375,6.618) P24(-11.366,6.618) P26(-12.339,6.618) P27(-12.814,6.262) P28(-13.289,6.618) P30(-14.262,6.618) P32(-15.253,6.618) P34(-16.226,6.618) P35(-16.701,6.262) P36(-17.176,6.618) P38(-18.15,6.618) P40(-19.119,6.479) P41(-19.721,6.479) P42(-20.433,6.479) P44(-21.144,6.479) P45(-21.855,6.479) P47(-22.566,6.479) P48(-23.277,6.479) P50(-23.951,6.479) T4(-1.677,7.426) T6(-2.351,7.452) T7(-3.062,7.452) T9(-3.773,7.452) T10(-4.484,7.452) T12(-5.196,7.452) T13(-5.907,7.452) T14(-6.618,7.452) T40(-19.01,7.452) T41(-19.721,7.452) T42(-20.433,7.452) T44(-21.144,7.452) T45(-21.855,7.452) T47(-22.566,7.452) T48(-23.277,7.452) T50(-23.951,7.426) U5(-1.995,7.927) U6(-2.706,7.927) U8(-3.418,7.927) U9(-4.129,7.927) U11(-4.84,7.927) U12(-5.551,7.927) U14(-6.262,7.927) U40(-19.366,7.927) U42(-20.077,7.927) U43(-20.788,7.927) U45(-21.499,7.927) U46(-22.211,7.927) U48(-22.922,7.927) U49(-23.633,7.927) V4(-1.677,8.428) V6(-2.351,8.402) V7(-3.062,8.402) V9(-3.773,8.402) V10(-4.484,8.402) V12(-5.196,8.402) V13(-5.907,8.402) V14(-6.618,8.402) V40(-19.01,8.402) V41(-19.721,8.402) V42(-20.433,8.402) V44(-21.144,8.402) V45(-21.855,8.402) V47(-22.566,8.402) V48(-23.277,8.402) V50(-23.951,8.428) Y4(-1.677,9.375) Y6(-2.351,9.375) Y7(-3.062,9.375) Y9(-3.773,9.375) Y10(-4.484,9.375) Y12(-5.196,9.375) Y13(-5.907,9.375) Y14(-6.618,9.375) Y40(-19.01,9.375) Y41(-19.721,9.375) Y42(-20.433,9.375) Y44(-21.144,9.375) Y45(-21.855,9.375) Y47(-22.566,9.375) Y48(-23.277,9.375) Y50(-23.951,9.375)
